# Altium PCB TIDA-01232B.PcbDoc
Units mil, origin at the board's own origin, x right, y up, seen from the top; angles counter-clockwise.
Board outline 3000 x 3000 mil, 4 copper layers (Top Layer, Signal Layer 1, Signal Layer 2, Bottom Layer), stack 64.4 mil thick; 78 components, 21 nets, 177 pads, 127 vias.
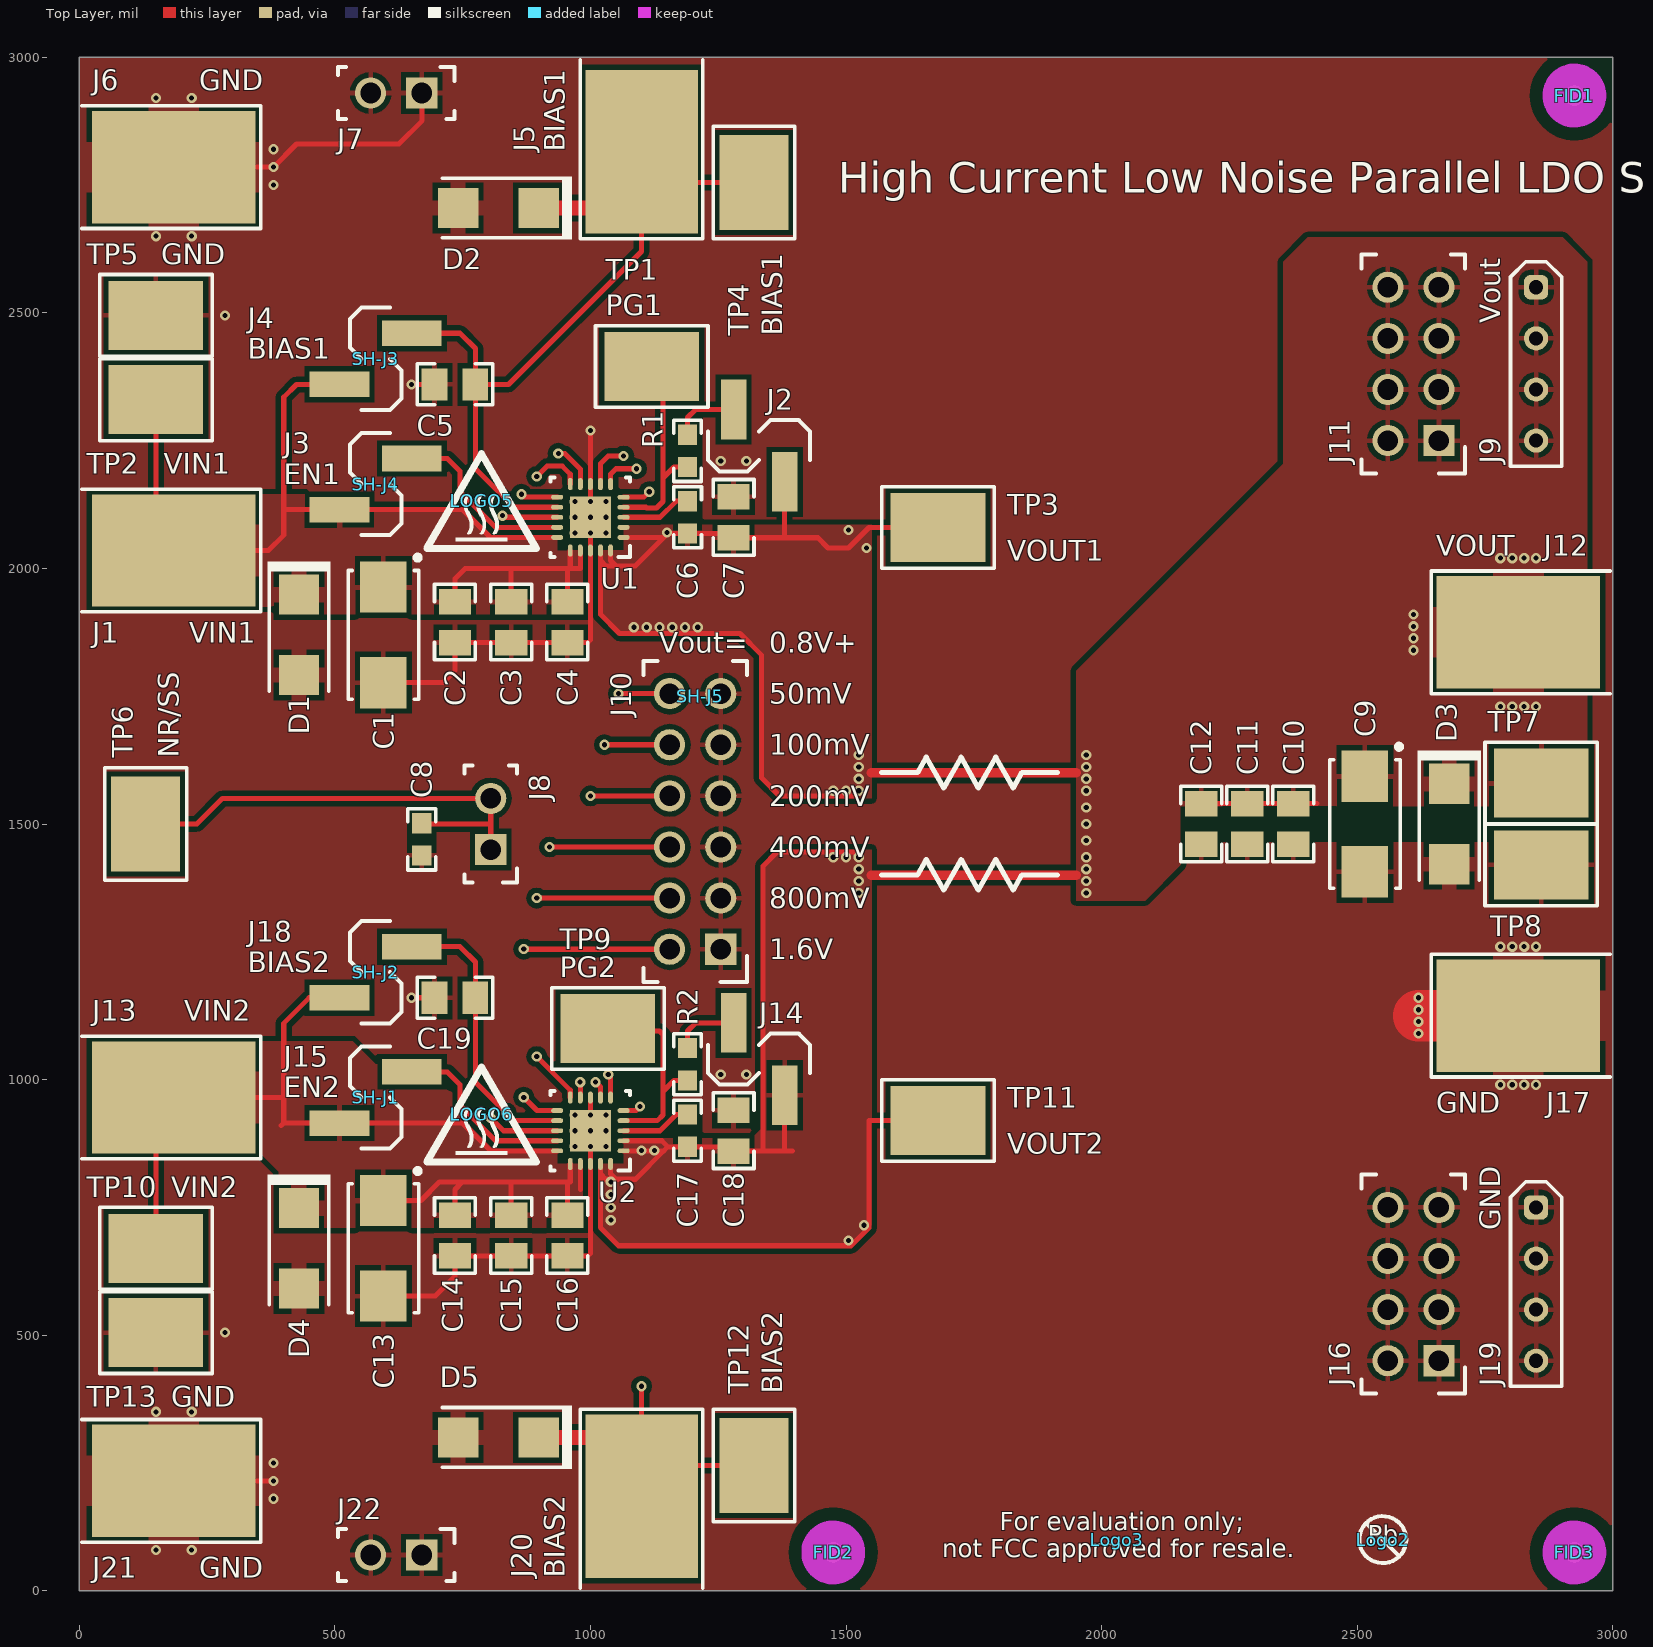
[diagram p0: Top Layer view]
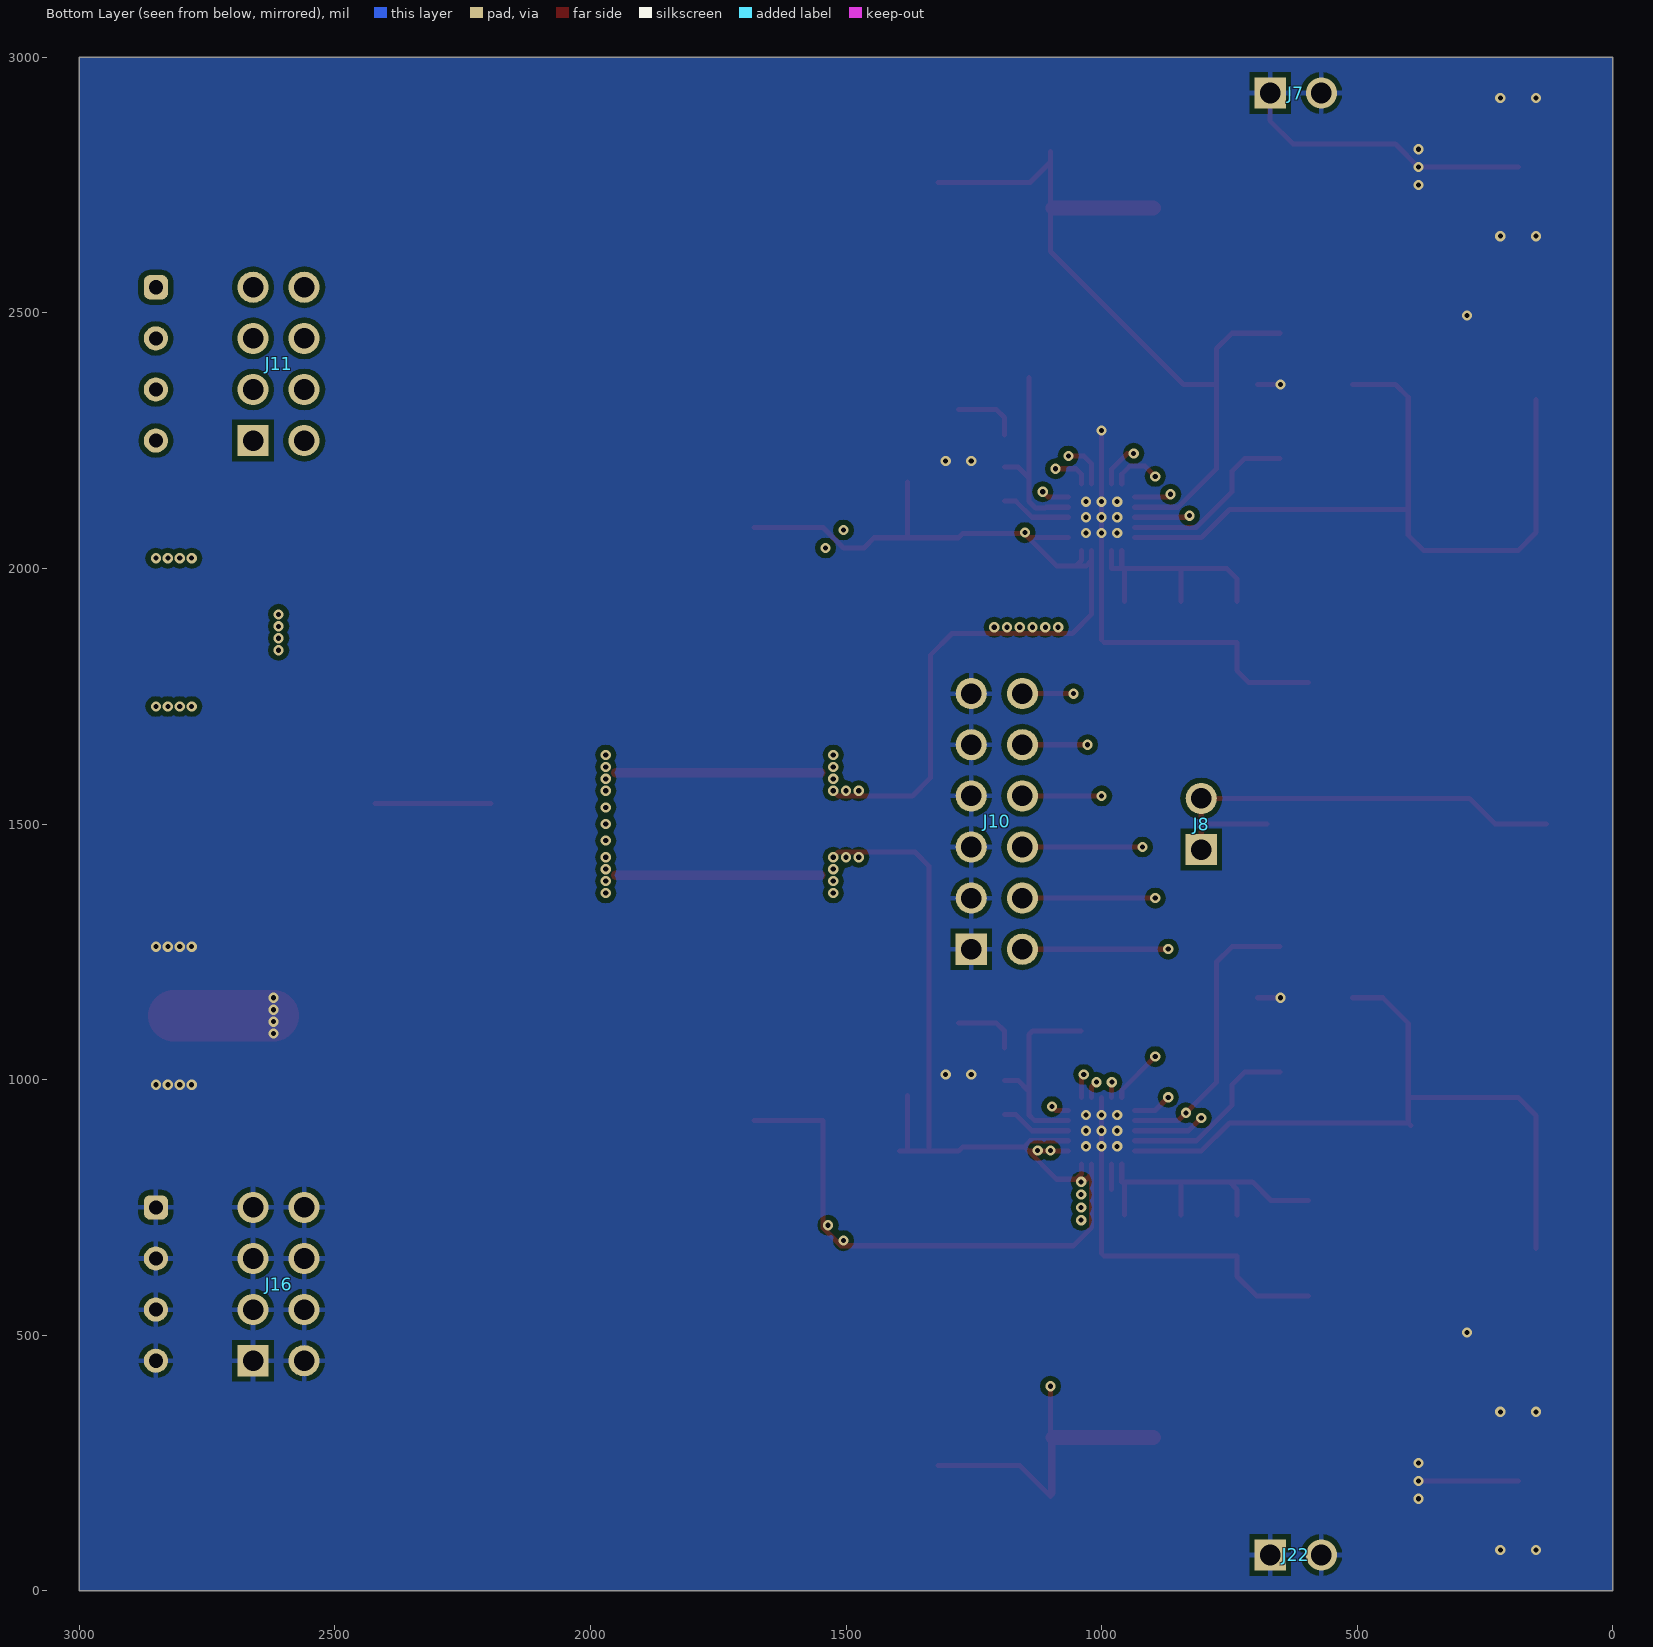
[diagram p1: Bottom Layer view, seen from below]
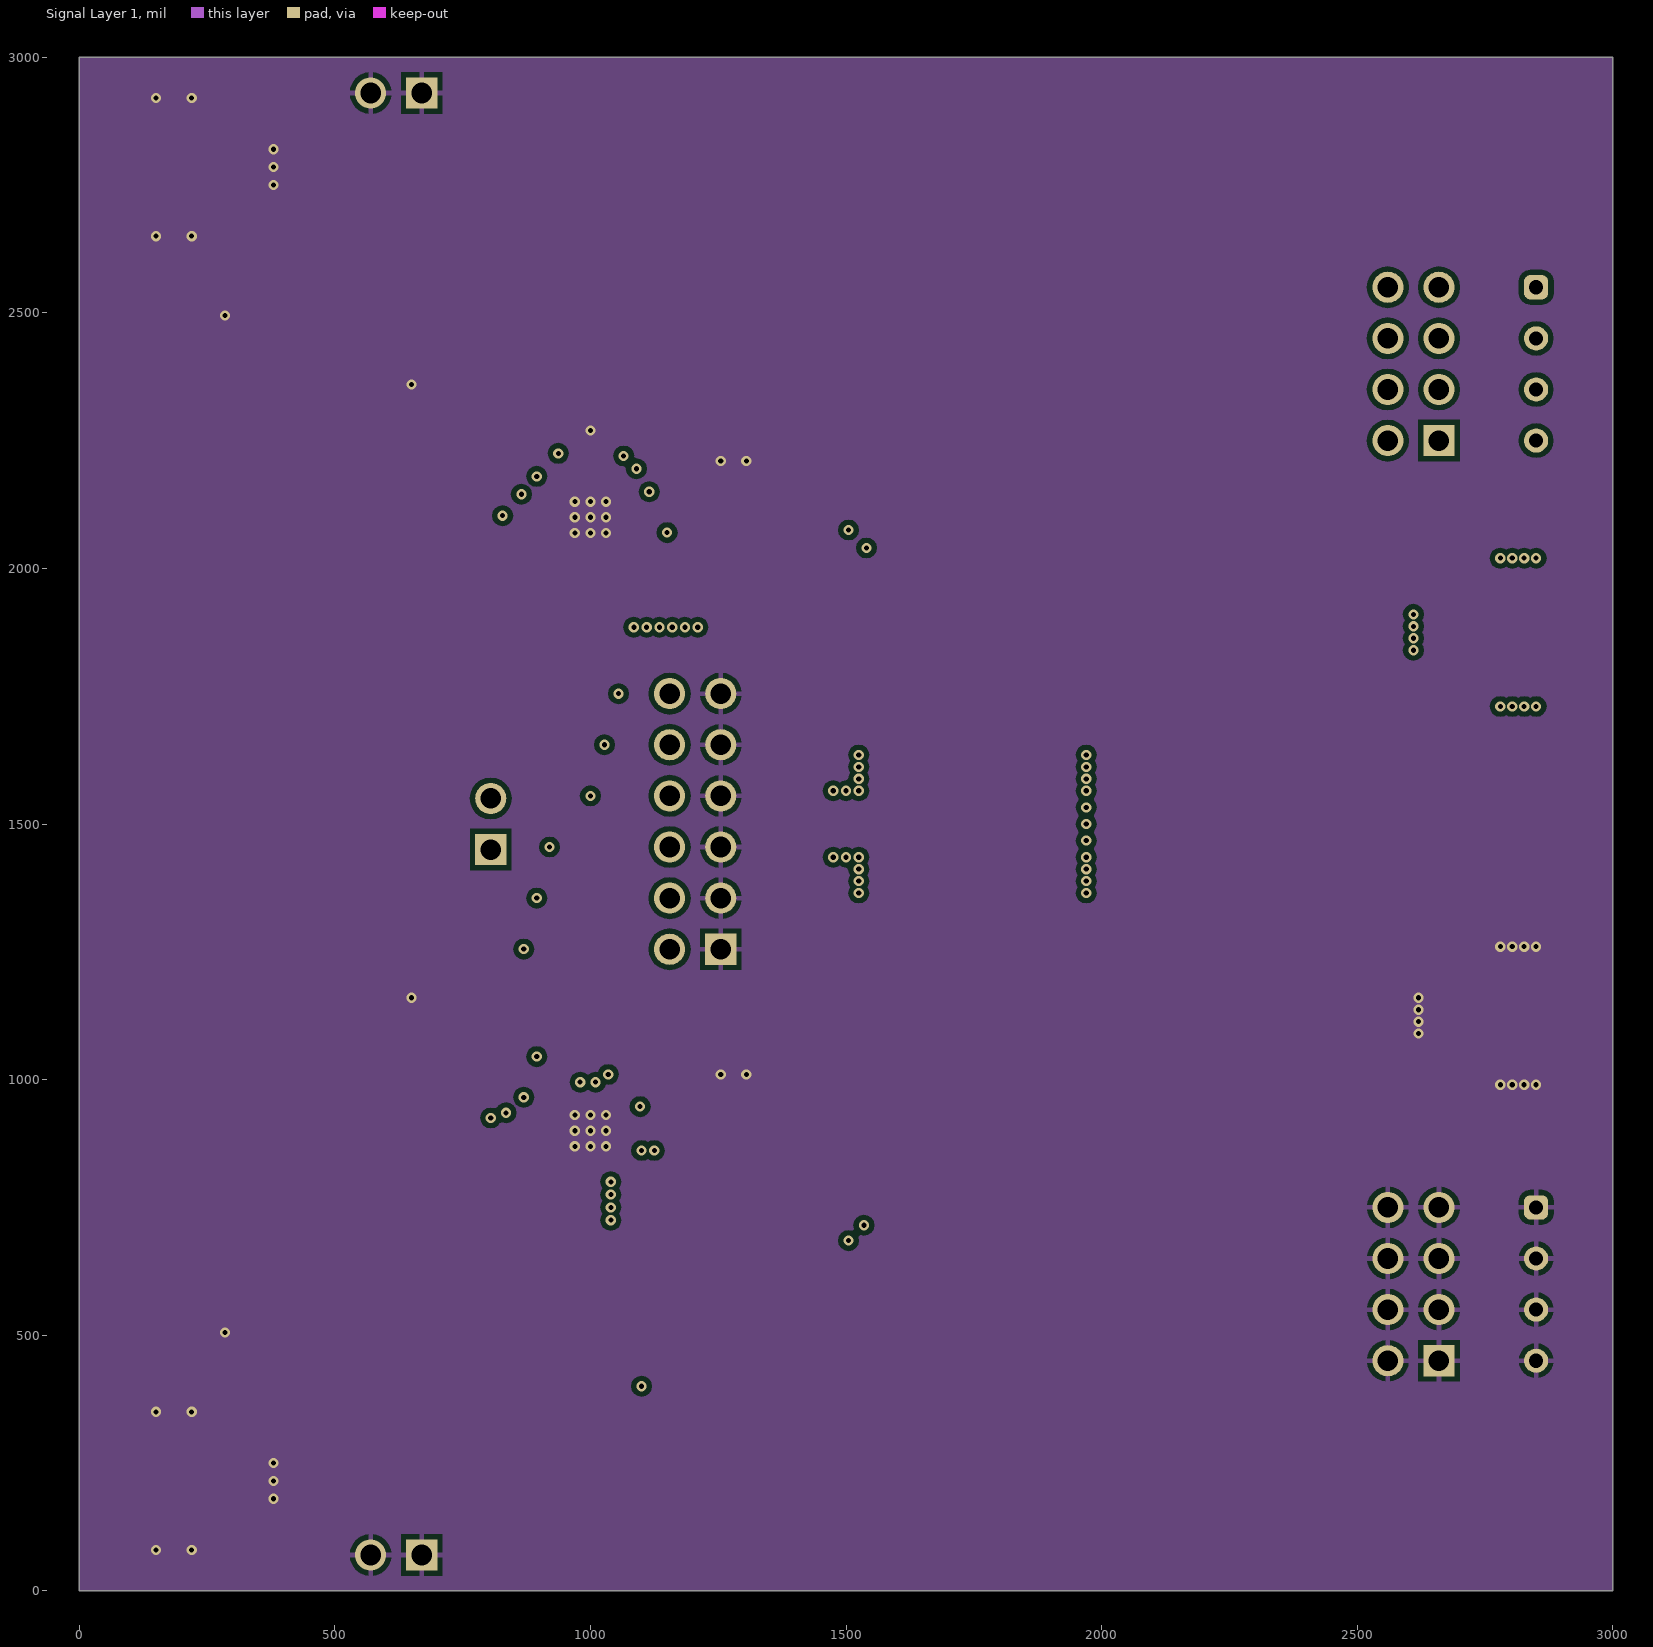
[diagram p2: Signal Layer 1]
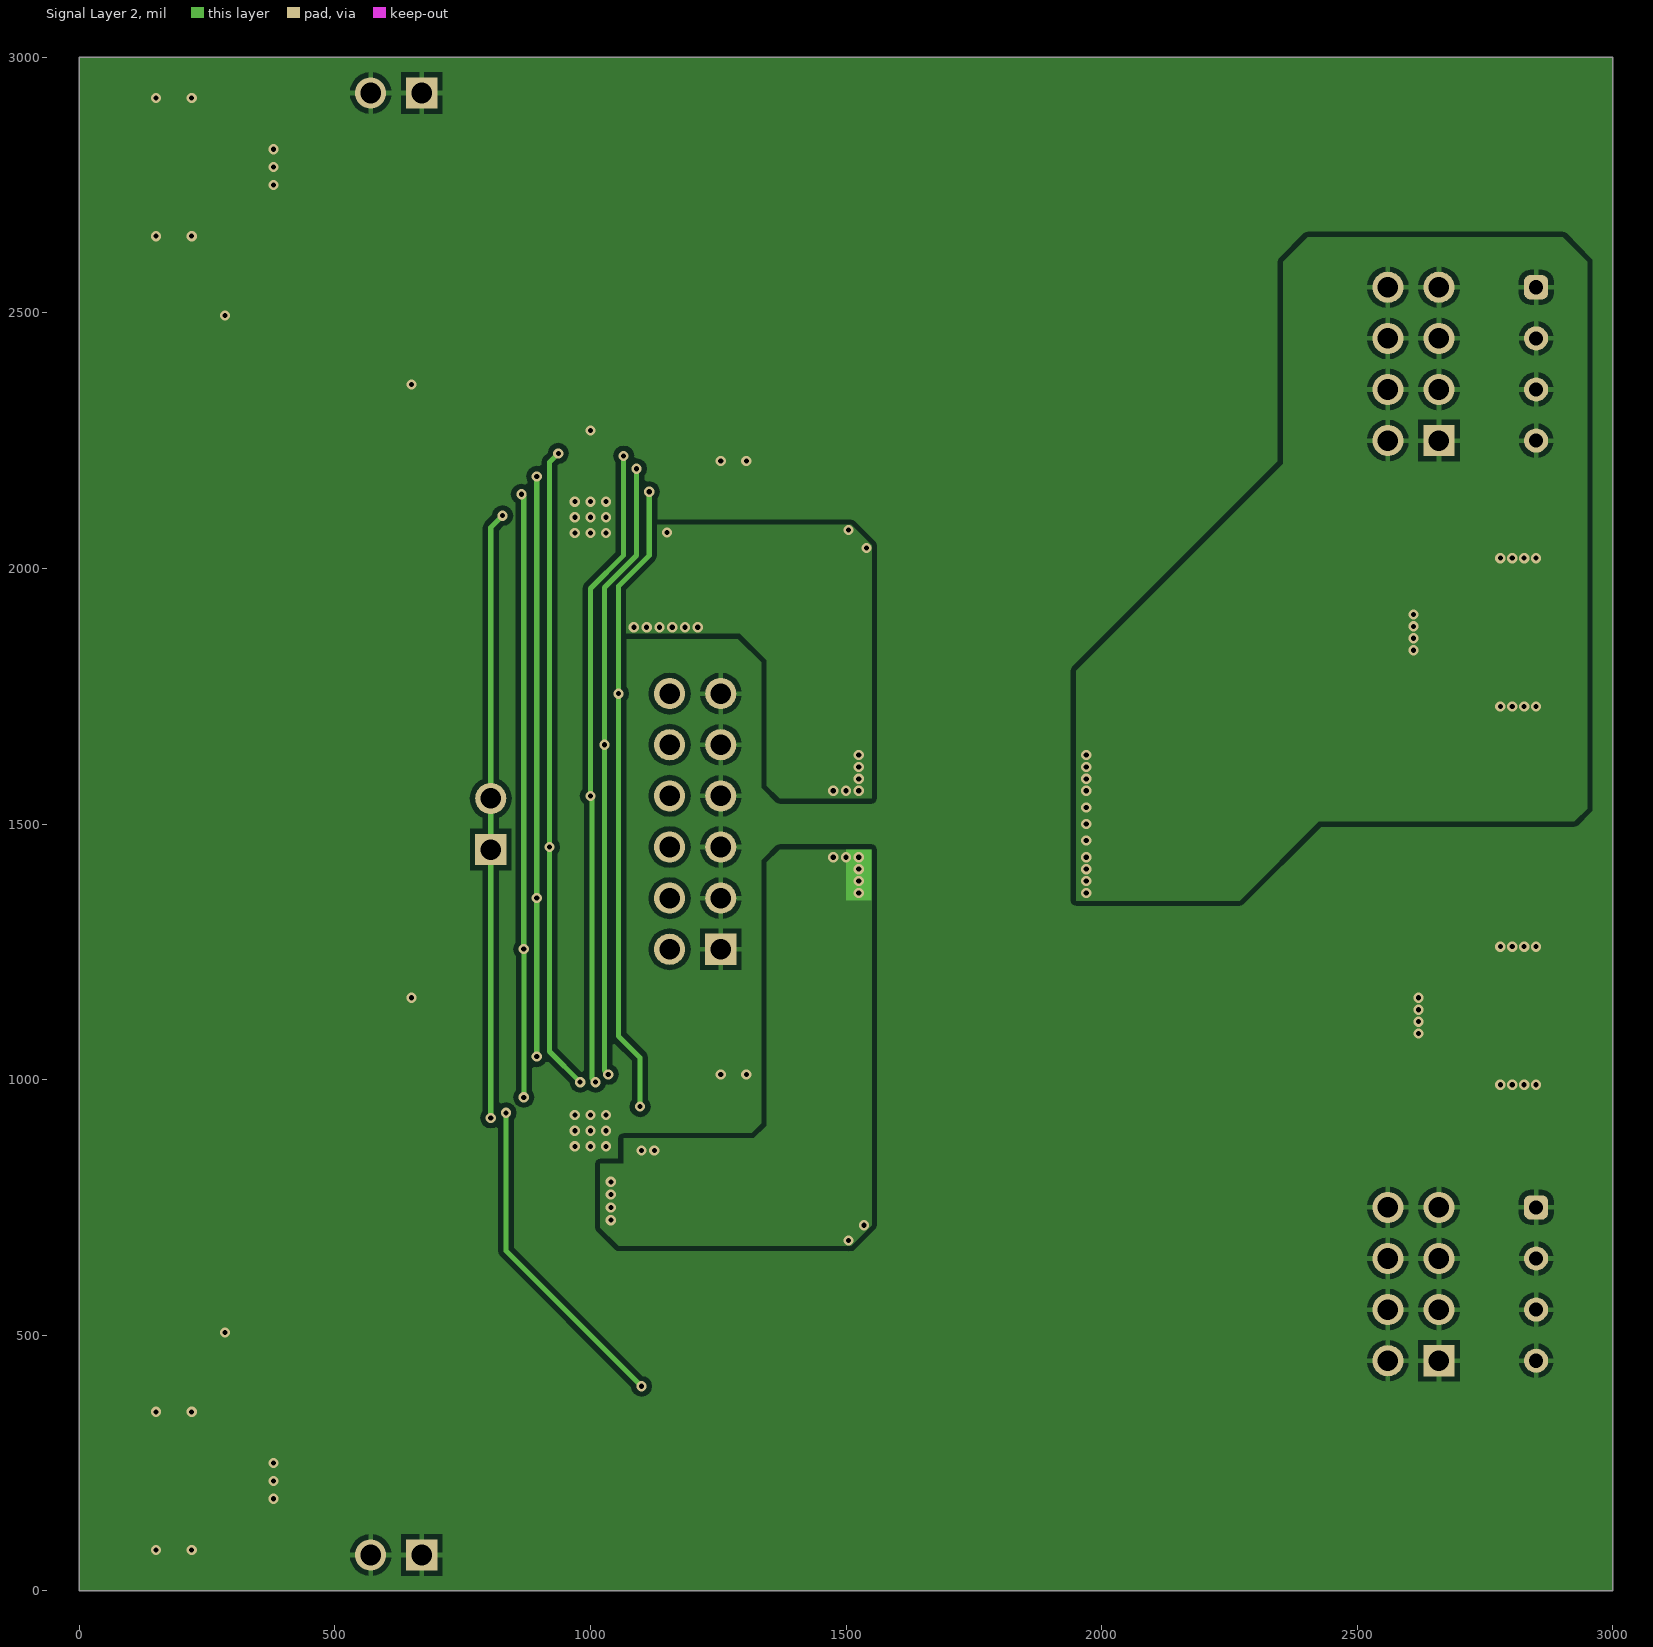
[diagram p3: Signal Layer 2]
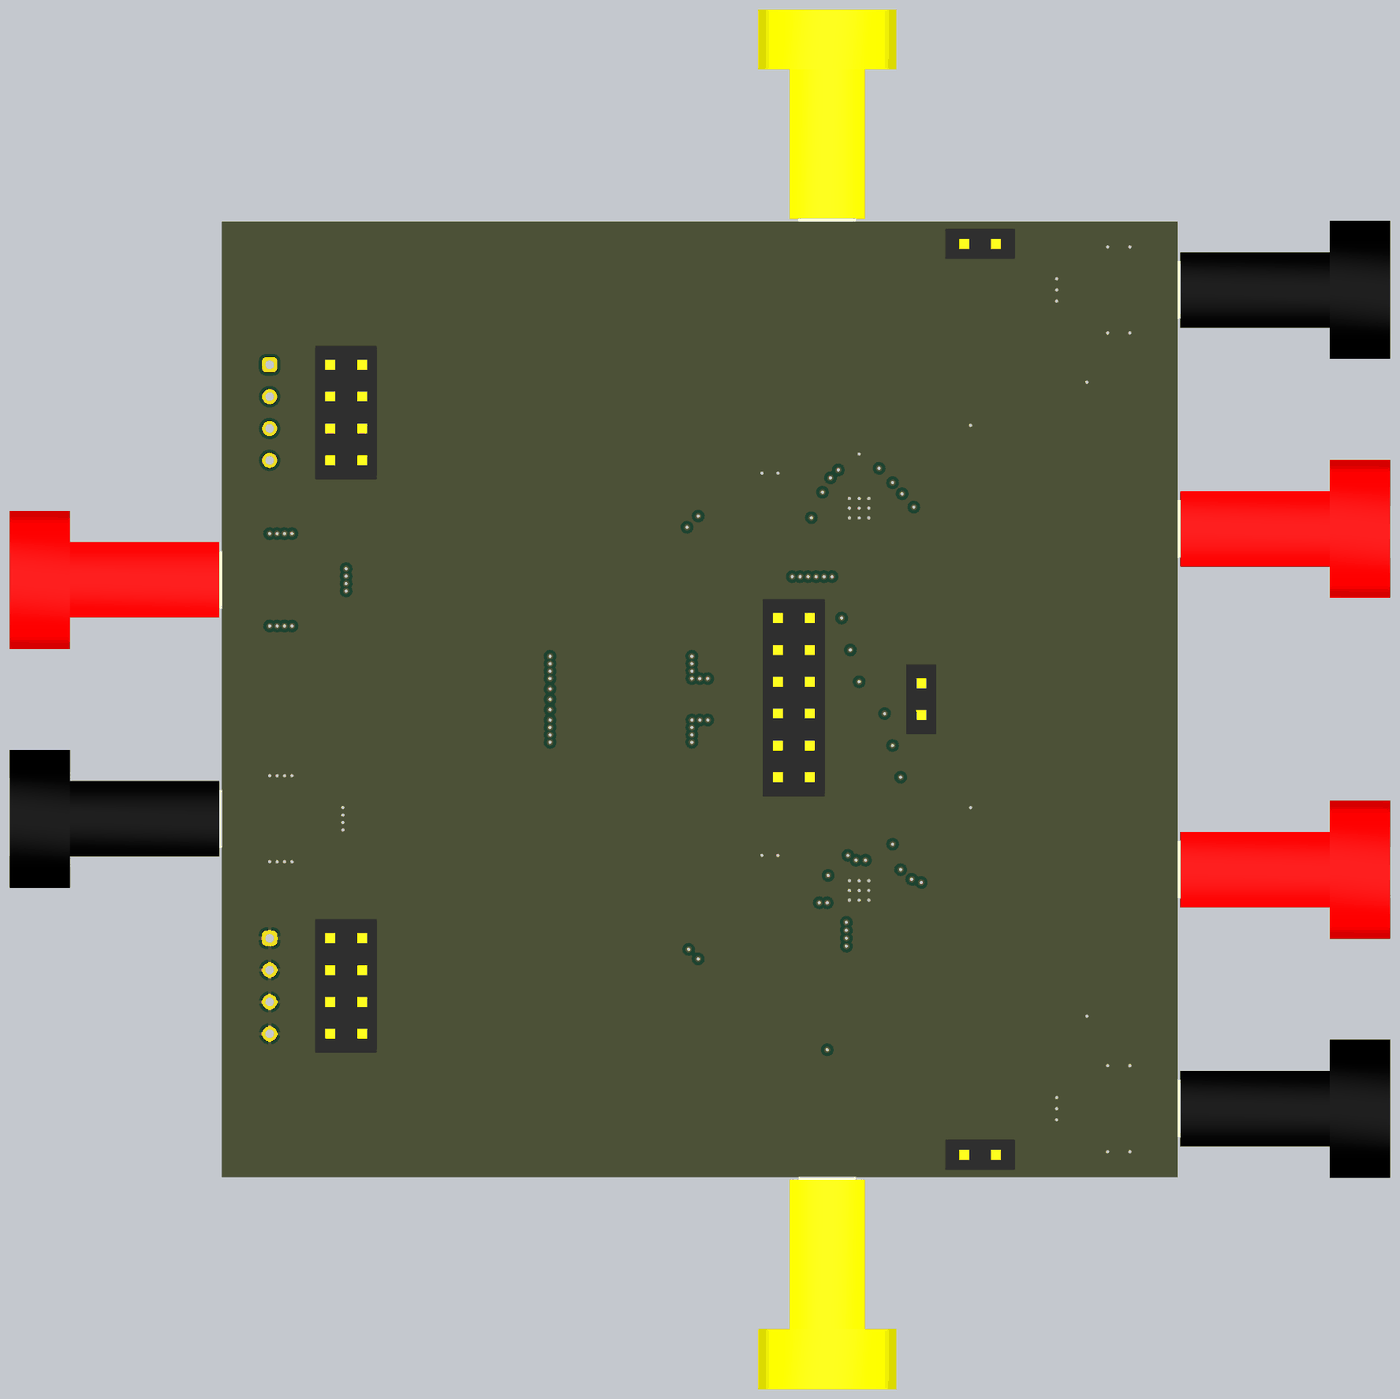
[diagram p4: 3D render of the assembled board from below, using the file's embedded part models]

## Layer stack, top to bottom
Top Solder: solder mask 0.4, Solder Resist, Dk 3.5
Top Layer: signal copper 2.8
Dielectric 1: core 8, Dk 4.2
Signal Layer 1: signal copper 1.4
Dielectric 2: prepreg 40, FR-4, Dk 4.2
Signal Layer 2: signal copper 1.4
Dielectric 3: core 8, Dk 4.2
Bottom Layer: signal copper 2.8
Bottom Solder: solder mask 1.4, Solder Resist, Dk 3.5

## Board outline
0,0 3000,0 3000,3000 0,3000

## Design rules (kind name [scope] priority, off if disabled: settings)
AcuteAngle [All] p1: minimum=4.50000000000000E+0001 checktracksonly=FALSE
AssemblyTestPointUsage [All] p1: valid=2
Clearance Clearance_Keepouts [((IsTrack Or IsArc) And Not InPoly) And IsFree and IsKeepOut vs ((IsTrack Or IsArc) And Not InPoly) And IsFree and IsKeepOut] p1: gap=0 ignorepadtopadclearanceinfootprint=FALSE
Clearance Clearance_BoardEdge_MountingHoles [OnCopper and InComponentClass('Mounting Holes') vs IsKeepOut] p2: gap=40 ignorepadtopadclearanceinfootprint=FALSE except(0: Arc-Hole Track-Hole SMDPad-Hole THPad-Hole Via-Hole Fill-Hole Poly-Hole Region-Hole Text-Hole)
Clearance Clearance_BoardEdge_Poly [OnCopper and InPoly vs IsKeepOut] p3: gap=25 ignorepadtopadclearanceinfootprint=FALSE except(0: Arc-Hole Track-Hole SMDPad-Hole THPad-Hole Via-Hole Fill-Hole Poly-Hole Region-Hole Text-Hole)
Clearance Clearance_BoardEdge [OnCopper and Not InComponentClass('Logo') and not InComponentClass('FiducialMark') and not InRegion(1000,500,4000,800) and Not IsKeepout vs IsKeepOut] p4: gap=5 ignorepadtopadclearanceinfootprint=FALSE except(0: Arc-Hole Track-Hole SMDPad-Hole THPad-Hole Via-Hole Fill-Hole Poly-Hole Region-Hole Text-Hole)
Clearance Clearance_Poly [InPolygon] p5: gap=10 ignorepadtopadclearanceinfootprint=FALSE except(0: Arc-Hole Track-Hole SMDPad-Hole THPad-Hole Via-Hole Fill-Hole Poly-Hole Region-Hole Text-Hole)
Clearance [All] p6: gap=7.87 ignorepadtopadclearanceinfootprint=FALSE except(0: Arc-Hole Track-Hole SMDPad-Hole THPad-Hole Via-Hole Fill-Hole Poly-Hole Region-Hole Text-Hole)
ComponentClearance ComponentClearance_MountingHoles_FiducialMarks [InComponentClass('Mounting Holes') vs InComponentClass('FiducialMark')] p1: gap=50 collisioncheckmode=3 verticalgap=10 showdistances=FALSE
ComponentClearance ComponentClearance_Shunt [InComponentClass('Header') vs InComponentClass('Shunt')] p2: gap=0 collisioncheckmode=3 verticalgap=0 showdistances=FALSE
ComponentClearance ComponentClearance_Shunt_1 [HasFootprint('SNT-100-BK-G')] p3: gap=0 collisioncheckmode=3 verticalgap=0 showdistances=FALSE
ComponentClearance ComponentClearance_Logo [InComponentClass('Logo')] p4: gap=50 collisioncheckmode=3 verticalgap=10 showdistances=FALSE
ComponentClearance ComponentClearance_ScrewToNut [(HasFootprint('NY PMS 440 0025 PH')) vs (HasFootprint('Keystone_1902C'))] p5: gap=5 collisioncheckmode=3 verticalgap=10 showdistances=FALSE
ComponentClearance ComponentClearance_MountingHoles [InComponentClass('Mounting Holes')] p6: gap=250 collisioncheckmode=3 verticalgap=100000 showdistances=FALSE
ComponentClearance ComponentClearance_SmallPassives [HasFootprint('0201*') or HasFootprint('0402*') or HasFootprint('0508') or HasFootprint('0603*') or HasFootprint('0612') or HasFootprint('0805*') or HasFootprint('0815*') or HasFootprint('0830*') or HasFootprint('1206*') or HasFootprint('1210*') or HasFootprint('1808*') or HasFootprint('1812*') or HasFootprint('1825*') or HasFootprint('2010*') or HasFootprint('2220*') or HasFootprint('2225*') or HasFootprint('2512*') or HasFootprint('2728*') or HasFootprint('3518*') vs HasFootprint('0201*') or HasFootprint('0402*') or HasFootprint('0508') or HasFootprint('0603*') or HasFootprint('0612') or HasFootprint('0805*') or HasFootprint('0815*') or HasFootprint('0830*') or HasFootprint('1206*') or HasFootprint('1210*') or HasFootprint('1808*') or HasFootprint('1812*') or HasFootprint('1825*') or HasFootprint('2010*') or HasFootprint('2220*') or HasFootprint('2225*') or HasFootprint('2512*') or HasFootprint('2728*') or HasFootprint('3518*')] p7: gap=20 collisioncheckmode=3 verticalgap=10 showdistances=FALSE
ComponentClearance ComponentClearance_THtoSMT [IsThruComponent vs IsSMTComponent] p8: gap=100 collisioncheckmode=3 verticalgap=30 showdistances=FALSE
ComponentClearance ComponentClearance_THtoTH [IsThruComponent vs IsThruComponent] p9: gap=118.11 collisioncheckmode=3 verticalgap=30 showdistances=FALSE
ComponentClearance [All] p10: gap=40 collisioncheckmode=3 verticalgap=10 showdistances=FALSE
DiffPairsRouting [All] p1: maxlimit=100 minlimit=10 mostfreqgap=10 toplayer_minwidth=15 toplayer_maxwidth=15 toplayer_prefwidth=15 midlayer1_minwidth=15 midlayer1_maxwidth=15 midlayer1_prefwidth=15 midlayer2_minwidth=15 midlayer2_maxwidth=15 midlayer2_prefwidth=15 bottomlayer_minwidth=15 bottomlayer_maxwidth=15 bottomlayer_prefwidth=15 maxuncoupledlength=1000
FabricationTestPointUsage TestPointUsage [All] p1: valid=2 allowmultiple=FALSE
FabricationTestpoint Testpoint [All] p1: side=3 testpointundercomponent=TRUE minsize=40 maxsize=100 preferedsize=60 minholesize=0 maxholesize=40 preferedholesize=32 testpointgrid=1 allowsidetop=TRUE allowsidebottom=TRUE usegrid=TRUE gridtolerance=0.01
FanoutControl Fanout_LCC [IsLCC] p1: bgadir=Out bgaviamode=Centered fanoutstyle=Auto fanoutdirection=Alternating viagrid=1 // Fanout_LCC (Default Rule)
FanoutControl Fanout_BGA [IsBGA] p2: bgadir=Out bgaviamode=Centered fanoutstyle=Auto fanoutdirection=Alternating viagrid=1 // Fanout_BGA (Default Rule)
FanoutControl Fanout_Default [All] p4: bgadir=Out bgaviamode=Centered fanoutstyle=Auto fanoutdirection=Alternating viagrid=1 // Fanout_Default (Default Rule)
FanoutControl Fanout_Small [(CompPinCount < 5)] p5: bgadir=Out bgaviamode=Centered fanoutstyle=Auto fanoutdirection=OutThenIn viagrid=1 // Fanout_Small (Default Rule)
HoleSize [All] p1: absolutevalues=TRUE maxlimit=251 minlimit=8 maxpercent=80.000 minpercent=20.000
MinimumAnnularRing MinimumAnnularRing_ThermalPadVias [IsVia and InAnyComponent] p1: minimumring=5
MinimumAnnularRing [All] p2: minimumring=5
MinimumSolderMaskSliver MinimumSolderMaskSliver_Logo [InComponentClass('Logo') vs InComponentClass('Logo')] p1: minsoldermaskwidth=0.7
MinimumSolderMaskSliver [All] p2: minsoldermaskwidth=3.94
PlaneClearance [All] p1: clearance=10
PlaneConnect [All] p1: planeconnectstyle=Direct reliefexpansion=10 reliefentries=4 reliefconductorwidth=10 reliefairgap=10
PolygonConnect TPS_thermals [HasFootprint('RGR0020A')] p1: connectstyle=Direct reliefconductorwidth=10 reliefentries=4 polygonreliefangle="90 Angle" airgapwidth=10
PolygonConnect VIAS [All vs IsVia] p2: connectstyle=Direct reliefconductorwidth=10 reliefentries=4 polygonreliefangle="90 Angle" airgapwidth=10
PolygonConnect BananaCon_Pow [HasFootprint('6091')] p3: connectstyle=Relief reliefconductorwidth=100 reliefentries=4 polygonreliefangle="90 Angle" airgapwidth=10
PolygonConnect BananaCon_GND [HasFootprint('6092')] p4: connectstyle=Relief reliefconductorwidth=100 reliefentries=4 polygonreliefangle="90 Angle" airgapwidth=10
PolygonConnect PolygonCon_ZD [HasFootprint('SMA')] p5: connectstyle=Relief reliefconductorwidth=30 reliefentries=4 polygonreliefangle="90 Angle" airgapwidth=10
PolygonConnect [All] p6: connectstyle=Relief reliefconductorwidth=10 reliefentries=4 polygonreliefangle="90 Angle" airgapwidth=10
RoutingVias ThermalPadVias [IsVia and InAnyComponent] p1: holewidth=8 width=18 viastyle="Through Hole" minholewidth=8 minwidth=18 maxholewidth=12.99 maxwidth=23.62
RoutingVias [All] p2: holewidth=8 width=18 viastyle="Through Hole" minholewidth=8 minwidth=18 maxholewidth=40 maxwidth=65
SilkToBoardRegionClearance [Not ((IsComment or IsDesignator) And (Hide <> 'False')) and not InRegion(1000,500,4000,800)] p1:
SilkToSilkClearance SilkToSilkClearance_Pb-FreeLogo [(HasFootprint('Pb-Free_Overlay_Medium') OR HasFootprint('Pb-Free_Overlay_Small')) vs (HasFootprint('Pb-Free_Overlay_Medium') OR HasFootprint('Pb-Free_Overlay_Small'))] p1: silktosilkclearance=0
SilkToSilkClearance [All] p2: silktosilkclearance=4
SilkToSolderMaskClearance SilkToComonentPadClearance [IsPad and InAnycomponent] p1: minsilkscreentomaskgap=5 clearancetoexposedcopper=TRUE
SilkToSolderMaskClearance "Silk to Solder Mask Opening" [All] p2: minsilkscreentomaskgap=4 clearancetoexposedcopper=FALSE
SolderMaskExpansion [All] p1: expansion=1.97
Width [All] p1: maxlimit=100 minlimit=6 preferedwidth=10 checkconnectedcopper=TRUE
14 further rules are at their usual default settings.

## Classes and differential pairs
component class FiducialMark: FID1 FID2 FID3
component class Header: J2 J3 J4 J14 J15 J18
component class TIDA-01232B_Hardware: FID1 FID2 FID3 Logo2 Logo3 LOGO5 LOGO6 SH-J1 SH-J2 SH-J3 SH-J4 SH-J5 ZZ1 ZZ2 ZZ3
component class AssemblyNote: ZZ1 ZZ2 ZZ3
component class TIDA-01232B: C1 C2 C3 C4 C5 C6 C7 C8 C9 C10 C11 C12 C13 C14 C15 C16 C17 C18 C19 D1 D2 D3 D4 D5 J1 J2 J3 J4 J5 J6 J7 J8 J9 J10 J11 J12 J13 J14 J15 J16 J17 J18 J19 J20 J21 J22 R1 R2 TP1 TP2 TP3 TP4 TP5 TP6 TP7 TP8 TP9 TP10 TP11 TP12 TP13 U1 U2
component class Shunt: SH-J1 SH-J2 SH-J3 SH-J4 SH-J5

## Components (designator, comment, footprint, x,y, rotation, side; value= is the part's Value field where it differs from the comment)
C1 "TPSC686K016R0200" 6032-28 595,1870 r270 top value=68uF
C2 "GRM21BR61C106KE15L" 0805_HV 735,1895 r270 top value=10uF
C3 "GRM21BR61C106KE15L" 0805_HV 845,1895 r270 top value=10uF
C4 "GRM219R60G476ME44D" 0805_HV 955,1895 r270 top value=47uF
C5 "GRM21BR61C106KE15L" 0805_HV 735,2360 r180 top value=10uF
C6 "GRM188R71H103KA01D" 0603 1190,2100 r270 top value=0.01uF
C7 "GRM219R60G476ME44D" 0805_HV 1280,2100 r90 top value=47uF
C8 "GRM188R71H103KA01D" 0603 670,1470 r270 top value=0.01uF
C9 "TPSC686K016R0200" 6032-28 2515,1500 r270 top value=68uF
C10 "GRM219R60G476ME44D" 0805_HV 2375,1500 r270 top value=47uF
C11 "GRM21BR61C106KE15L" 0805_HV 2285,1500 r270 top value=10uF
C12 "GRM21BR61C106KE15L" 0805_HV 2195,1500 r270 top value=10uF
C13 "TPSC686K016R0200" 6032-28 595,670 r270 top value=68uF
C14 "GRM21BR61C106KE15L" 0805_HV 735,695 r270 top value=10uF
C15 "GRM21BR61C106KE15L" 0805_HV 845,695 r270 top value=10uF
C16 "GRM219R60G476ME44D" 0805_HV 955,695 r270 top value=47uF
C17 "GRM188R71H103KA01D" 0603 1190,900 r90 top value=0.01uF
C18 "GRM219R60G476ME44D" 0805_HV 1280,900 r90 top value=47uF
C19 "GRM21BR61C106KE15L" 0805_HV 735,1160 r180 top value=10uF
D1 "SMAZ5V6-13-F" SMA 430,1870 r270 top value=5.6V
D2 "SMAZ5V6-13-F" SMA 820,2705 r180 top value=5.6V
D3 "SMAZ5V6-13-F" SMA 2680,1500 r270 top value=5.6V
D4 "SMAZ5V6-13-F" SMA 430,670 r270 top value=5.6V
D5 "SMAZ5V6-13-F" SMA 820,300 r180 top value=5.6V
FID1 "Fiducial" Fiducial10-30 2925,2925 r0 top
FID2 "Fiducial" Fiducial10-30 1475,75 r0 top
FID3 "Fiducial" Fiducial10-30 2925,75 r0 top
J1 "VIN1" 6091 0,2035 r0 top
J2 "PG1" Molex_87898-0204 1330,2240 r0 top
J3 "EN1" Molex_87898-0204 580,2165 r270 top
J4 "BIAS1" Molex_87898-0204 580,2410 r270 top
J5 "BIAS1" CONN_108-0907-001 1100,3000 r270 top
J6 "GND" 6092 0,2785 r0 top
J7 "SSQ-102-03-G-S" Samtec_SSQ-102-03-x-S 620,2930 r180 bottom
J8 "SSQ-102-03-G-S" Samtec_SSQ-102-03-x-S 805,1500 r90 bottom
J9 "Vout" Mill-Max_342-xx-104-00-591000 2850,2400 r270 top
J10 "SSQ-106-03-G-D" Samtec_SSQ-106-03-x-D 1205,1505 r90 bottom
J11 "SSQ-104-03-G-D" Samtec_SSQ-104-03-x-D 2610,2400 r90 bottom
J12 "VOUT" 6091 3000,1875 r180 top
J13 "VIN2" 6091 0,965 r0 top
J14 "PG2" Molex_87898-0204 1330,1040 r0 top
J15 "EN2" Molex_87898-0204 580,965 r270 top
J16 "SSQ-104-03-G-D" Samtec_SSQ-104-03-x-D 2610,600 r90 bottom
J17 "GND" 6092 3000,1125 r180 top
J18 "BIAS2" Molex_87898-0204 580,1210 r270 top
J19 "GND" Mill-Max_342-xx-104-00-591000 2850,600 r270 top
J20 "BIAS2" CONN_108-0907-001 1100,0 r90 top
J21 "GND" 6092 0,215 r0 top
J22 "SSQ-102-03-G-S" Samtec_SSQ-102-03-x-S 620,70 r180 bottom
Logo2 "Pb-Free Symbol" Pb-Free_Overlay_Small 2550,100 r0 top
Logo3 "FCC disclaimer" FCC_disclaimer_stacked 2030,100 r0 top
LOGO5 "CAUTION HOT SURFACE" IEC_HotSurface_Small 787,2132 r0 top
LOGO6 "CAUTION HOT SURFACE" IEC_HotSurface_Small 787,932 r0 top
R1 "CRCW060310K0FKEA" 0603 1190,2230 r90 top value=10.0k
R2 "CRCW060310K0FKEA" 0603 1190,1030 r90 top value=10.0k
SH-J1 "969102-0000-DA" SNT-100-BK-G 580,965 r90 top value=1x2
SH-J2 "969102-0000-DA" SNT-100-BK-G 580,1210 r90 top value=1x2
SH-J3 "969102-0000-DA" SNT-100-BK-G 580,2410 r90 top value=1x2
SH-J4 "969102-0000-DA" SNT-100-BK-G 580,2165 r90 top value=1x2
SH-J5 "969102-0000-DA" SNT-100-BK-G 1214.8,1750 r180 top value=1x2
TP1 "PG1" Testpoint_Keystone_Compact 1120,2395 r180 top value=SMT
TP2 "VIN1" Testpoint_Keystone_Compact 150,2330 r180 top value=SMT
TP3 "VOUT1" Testpoint_Keystone_Compact 1680,2080 r180 top value=SMT
TP4 "BIAS1" Testpoint_Keystone_Compact 1320,2755 r270 top value=SMT
TP5 "GND" Testpoint_Keystone_Compact 150,2495 r180 top value=SMT
TP6 "NR/SS" Testpoint_Keystone_Compact 130,1500 r90 top value=SMT
TP7 "VOUT" Testpoint_Keystone_Compact 2860,1580 r180 top value=SMT
TP8 "GND" Testpoint_Keystone_Compact 2860,1420 r180 top value=SMT
TP9 "PG2" Testpoint_Keystone_Compact 1034.26,1100 r180 top value=SMT
TP10 "VIN2" Testpoint_Keystone_Compact 150,670 r180 top value=SMT
TP11 "VOUT2" Testpoint_Keystone_Compact 1680,920 r180 top value=SMT
TP12 "BIAS2" Testpoint_Keystone_Compact 1320,245 r270 top value=SMT
TP13 "GND" Testpoint_Keystone_Compact 150,505 r0 top value=SMT
U1 "TPS7A8500RGRR" RGR0020A 1000,2100 r180 top
U2 "TPS7A8500RGRR" RGR0020A 1000,900 r180 top
ZZ1 "These assemblies are ESD sensitive, ESD precautions shall be observed." AssemblyNote -505,3930 r0 top
ZZ2 "These assemblies must be clean and free from flux and all contaminants. Use of no clean flux is not acceptable." AssemblyNote -505,4172.5 r0 top
ZZ3 "These assemblies must comply with workmanship standards IPC-A-610 Class 2, unless otherwise specified." AssemblyNote -505,4415 r0 top

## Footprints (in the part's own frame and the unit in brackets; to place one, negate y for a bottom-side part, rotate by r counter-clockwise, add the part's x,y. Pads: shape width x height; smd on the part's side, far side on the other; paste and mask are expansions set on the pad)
0603 [mm] "0603 from SM-752 data"
  rect 1x0.95 smd: 1(-0.8,0) 2(0.8,0)
  silkscreen extent -1.52,-0.69 1.52,0.69, body extent -0.87,-0.47 0.87,0.47, height 1
0805_HV [mil] "0805 with 30mil clearance between pads"
  rect 50x63 smd: 1(-40,0) 2(40,0)
  silkscreen extent -74,-40 74,40, body extent -43,-29 43,29, height 57
6032-28 [mm] "Medium Density IPC based on Vishay Sprague 293D datasheet."
  rect 2.55x2.3 smd: 1(-2.375,0) 2(2.375,0)
  silkscreen extent -3.96,-1.75 3.2,1.83, body extent -3.15,-1.75 3.15,1.75, height 2.8
6091 [mil] "Keystone Insulated End Launch Banana Jack"
  rect 320x220 smd: 1(185,0)
  silkscreen extent 5,-120 355,120, body extent -666,-216 271,216, height 227
6092 [mil] "Keystone Insulated End Launch Banana Jack"
  rect 320x220 smd: 1(185,0)
  silkscreen extent 5,-120 355,120, body extent -666,-216 271,216, height 227
AssemblyNote [mil] "Assembly Note"
CONN_108-0907-001 [mil] "Keystone Insulated End Launch Banana Jack"
  rect 320x220 smd: 1(185,0)
  silkscreen extent 5,-120 355,120, body extent -666,-216 271,216, height 227
FCC_disclaimer_stacked [mil]
Fiducial10-30 [mm]
  round 1 smd mask+1: 1(0,0)
  Top Layer keep-out circle w1.678: c0,0 r0.75
IEC_HotSurface_Small [mil]
  silkscreen extent -107,-93 107,92
Mill-Max_342-xx-104-00-591000 [mm] "Mill-Max"
  rrect50% 1.2x1.2 hole 0.7: 1(-3.81,0)
  round 1.2 hole 0.7: 2(-1.27,0) 3(1.27,0) 4(3.81,0)
  silkscreen extent -5.08,-1.27 5.08,1.27, body extent -5.08,-1.27 5.08,1.27, height 8.51
Molex_87898-0204 [mm] "Header, 2.54 mm, 2x1, R/A, SMT"
  rect 1.27x2.96 smd: 1(-1.27,1.8) 2(1.27,-1.8)
  silkscreen extent -2.54,-1.27 2.54,1.27, body extent -2.54,-2.4 2.54,2.4, height 9.65
Pb-Free_Overlay_Small [mil]
  silkscreen extent -46,-46 46,46
RGR0020A [mm] "QFN, 20-Leads, Body 3.5x3.5mm, Pitch 0.5mm, Thermal Pad 2.05x2.05mm, TI Recommended"
  oval 0.6x0.24 smd: 1(-1.65,1) 2(-1.65,0.5) 3(-1.65,0) 4(-1.65,-0.5) 5(-1.65,-1) 11(1.65,-1) 12(1.65,-0.5) 13(1.65,0) 14(1.65,0.5) 15(1.65,1)
  oval 0.24x0.6 smd: 6(-1,-1.65) 7(-0.5,-1.65) 8(0,-1.65) 9(0.5,-1.65) 10(1,-1.65) 16(1,1.65) 17(0.5,1.65) 18(0,1.65) 19(-0.5,1.65) 20(-1,1.65)
  rect 2.05x2.05 smd paste-1.025: 21(0,0)
  silkscreen extent -1.97,-1.97 1.97,1.97, body extent -1.83,-1.83 1.83,1.83, height 1.01
Samtec_SSQ-102-03-x-S [mm] "Receptacle, 2.54mm, 2x1, TH"
  rect 1.55x1.55 hole 1.02: 1(-1.27,0)
  round 1.55 hole 1.02: 2(1.27,0)
  body extent -2.79,-1.21 2.79,1.21, height 8.51
Samtec_SSQ-104-03-x-D [mm] "Receptacle, 2.54mm, 4x2, TH"
  rect 1.55x1.55 hole 1.02: 1(-3.81,1.27)
  round 1.55 hole 1.02: 2(-3.81,-1.27) 3(-1.27,1.27) 4(-1.27,-1.27) 5(1.27,1.27) 6(1.27,-1.27) 7(3.81,1.27) 8(3.81,-1.27)
  body extent -5.33,-2.48 5.33,2.48, height 8.51
Samtec_SSQ-106-03-x-D [mm] "Receptacle, 2.54mm, 6x2, TH"
  rect 1.55x1.55 hole 1.02: 1(-6.35,1.27)
  round 1.55 hole 1.02: 2(-6.35,-1.27) 3(-3.81,1.27) 4(-3.81,-1.27) 5(-1.27,1.27) 6(-1.27,-1.27) 7(1.27,1.27) 8(1.27,-1.27) 9(3.81,1.27) 10(3.81,-1.27) 11(6.35,1.27) 12(6.35,-1.27)
  body extent -7.87,-2.48 7.87,2.48, height 8.51
SMA [mm] "Molded Diode, 2-Leads, Body 4.3x2.6mm, IPC Medium Density, based on OnSemi component dimensions and land pattern"
  rect 2x2 smd: 1(-2,0) 2(2,0)
  silkscreen extent -3.66,-1.57 2.79,1.57, body extent -2.6,-1.3 2.6,1.3, height 2.42
SNT-100-BK-G [mil] "Samtec STEP model"
  round 1 on Mech3: 0(0,0)
  body extent -100,-50 100,50, height 344
Testpoint_Keystone_Compact [mil] "Compact SMT test point"
  rect 185x135 smd: 1(0,0)
  silkscreen extent -110,-80 110,80, body extent -75,-56 75,56, height 91

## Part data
C1 C9 C13: "CAP, TA, 68 µF, 16 V, +/- 10%, 0.2 ohm, SMD", Cap_Case=C, Manufacturer=AVX, Supplier Part Number 1=478-1774-1-ND, Tolerance_%=10, Value1="0.2 ohm", Value2=16V, ValueDisplayed=68µF
C2 C3 C5 C11 C12 C14 C15 C19: "CAP, CERM, 10 µF, 16 V, +/- 10%, X5R, 0805", Cap_Case=0805, Manufacturer=MuRata, Supplier Part Number 1=490-3886-1-ND, TempCo=X5R, Tolerance_%=10, Value1="0.008 ohm", Value2=16V, ValueDisplayed=10µF
C4 C7 C10 C16 C18: "CAP, CERM, 47 µF, 4 V, +/- 20%, X5R, 0805", Cap_Case=0805, Manufacturer=MuRata, Supplier Part Number 1=490-9949-2-ND, TempCo=X5R, Tolerance_%=20, Value1=Unknown, Value2=4V, ValueDisplayed=47µF
C6 C8 C17: "CAP, CERM, 0.01 µF, 50 V, +/- 10%, X7R, 0603", Cap_Case=0603, Manufacturer=MuRata, Supplier Part Number 1=490-1512-1-ND, TempCo=X7R, Tolerance_%=10, Value1=Unknown, Value2=50V, ValueDisplayed=0.01µF
D1 D2 D3 D4 D5: "Diode, Zener, 5.6 V, 1 W, SMA", Manufacturer="Diodes Inc.", Power_W=1, Supplier Part Number 1=SMAZ5V6-FDICT-ND, Value1=1W
FID1 FID2 FID3: "Fiducial mark.  There is nothing to buy or mount.", Manufacturer=N/A
J1 J12 J13: library part 6091, "Standard Banana Jack, Insulated, Red", Manufacturer=Keystone, Supplier Part Number 1=6091K-ND
J2 J3 J4 J14 J15 J18: library part 87898-0204, "Header, 2.54 mm, 2x1, Gold, R/A, SMT", Manufacturer=Molex, Supplier Part Number 1=WM9852-ND
J5 J20: library part 108-0907-001, "BANANA JACK, 15A, Insulated, Nylon,Yellow", Manufacturer="Emerson Network Power", Supplier Part Number 1=J154-ND
J6 J17 J21: library part 6092, "Standard Banana Jack, Insulated, Black", Manufacturer=Keystone, Supplier Part Number 1=6092K-ND
J7 J8 J22: "Receptacle, 2.54mm, 2x1, Gold, TH", Color=Black, Current_A=6.3, Manufacturer=Samtec, Supplier Part Number 1=SAM1198-02-ND
J9 J19: library part 342-10-104-00-591000, "Header, 100mil, 4x1, Gold, TH", Manufacturer=Mill-Max, Supplier Part Number 1=ED10004-ND
J10: "Receptacle, 2.54mm, 6x2, Gold, TH", Color=Black, Current_A=6.3, Manufacturer=Samtec, Supplier Part Number 1=SAM1196-06-ND
J11 J16: "Receptacle, 2.54mm, 4x2, Gold, TH", Color=Black, Current_A=6.3, Manufacturer=Samtec, Supplier Part Number 1=SAM1196-04-ND
Logo2: library part Pb-Free
Logo3: library part FCC_disclaimer, "FCC_disclaimer"
LOGO5 LOGO6: library part IEC_HotSurface, "IEC 61010-1 Hot Surface Warning"
R1 R2: "RES, 10.0 k, 1%, 0.1 W, 0603", Manufacturer=Vishay-Dale, Power_W=0.1, Supplier Part Number 1=541-10.0KHCT-ND, TempCo="100 ppm/C", Tolerance_%=1, Value1=1%, Value2=0.1W, Value_Code=10k0, ValueDisplayed=10.0k
SH-J1 SH-J2 SH-J3 SH-J4 SH-J5: "Shunt, 100mil, Gold plated, Black", Alternate Manufacturer=Samtec, Alternate PartNumber=SNT-100-BK-G, Manufacturer=3M, Supplier Part Number 1=3M9580-ND
TP1 TP2 TP3 TP4 TP5 TP6 TP7 TP8 TP9 TP10 TP11 TP12 TP13: library part 5016, "Test Point, Compact, SMT", Manufacturer=Keystone, Supplier Part Number 1=5016KCT-ND
U1 U2: "4-A, 6-µVRMS, RF, LDO Voltage Regulator, RGR0020A", Alternate Manufacturer="Texas Instruments", Alternate PartNumber=TPS7A8500RGRT
ZZ1 ZZ2 ZZ3: library part AssemblyNote, Alternate Manufacturer=-

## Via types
v1: diameter 20, hole 10, Top Layer to Bottom Layer, tented both sides, 127 vias

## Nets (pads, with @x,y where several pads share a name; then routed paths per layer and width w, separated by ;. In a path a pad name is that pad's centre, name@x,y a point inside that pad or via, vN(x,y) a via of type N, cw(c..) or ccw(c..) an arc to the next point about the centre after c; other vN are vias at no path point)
GND: C1.2 C2.2 C3.2 C4.2 C5.2 C7.2 C8.2 C9.2 C10.2 C11.2 C12.2 C13.2 C14.2 C15.2 C16.2 C18.2 C19.2 D1.2 D2.2 D3.2 D4.2 D5.2 J6.1 J7.1 J7.2 J10.1 J10.3 J10.5 J10.7 J10.9 J10.11 J16.1 J16.2 J16.3 J16.4 J16.5 J16.6 J16.7 J16.8 J17.1 J19.1 J19.2 J19.3 J19.4 J21.1 J22.1 J22.2 TP5.1 TP8.1 TP13.1 U1.8 U1.18 U1.21 U2.8 U2.18 U2.21 | length 2693.3
  Top Layer w10: J21.1 v1(380,215) ; J6.1 v1(380,2785) 425,2830 529.13,2830 625,2830 670.87,2875.87 J7.1@670.87,2930 ; C13.2 696.5,576.5 735,615 C14.2 C15.2 C16.2 995,655 ; C1.2 711.5,1776.5 735,1800 C2.2 C3.2 C4.2 995,1855 ; v1(650,1160) C19.2 ; v1(650,2360) C5.2 ; 1000,660 U2.8 ; 1000,1860 U1.18 v1(1000,2069.49) v1(1000,2100) v1(1000,2130.51) U1.8 v1(1000,2270)
  Top Layer w100: 2620,1125 J17.1
  other v1: 150,80 220,80 380,180 380,250 150,350 220,350 285,505 969.49,869.49 1000,869.49 1030.51,869.49 969.49,900 1000,900 1030.51,900 969.49,930.51 1000,930.51 1030.51,930.51 2780,990 2803.33,990 2826.67,990 2850,990 1255,1010 1305,1010 2620,1090 2620,1113.33 2620,1136.67 2620,1160 2780,1260 2803.33,1260 2826.67,1260 2850,1260 969.49,2069.49 1030.51,2069.49 969.49,2100 1030.51,2100 969.49,2130.51 1030.51,2130.51 1255,2210 1305,2210 285,2495 150,2650 220,2650 380,2750 380,2820 150,2920 220,2920
NetC1_1: C1.1 C2.1 C3.1 C4.1 D1.1 J1.1 J3.2 J4.2 TP2.1 U1.15 U1.16 U1.17 | length 1982.7
  Top Layer w10: TP2.1 150,2070 J1.1 370,2035 400,2065 400,2335 425,2360 J4.2 ; 400,2115 750,2115 804.37,2060.63 U1.15 ; C2.1 735,1980 755,2000 845,2000 ; C3.1 845,2000 ; C4.1 955,2000 ; U1.16 960.63,2000 ; U1.17 980.31,2000 960.63,2000 ; 845,2000 955,2000 ; 955,2000 960.63,2000
NetC5_1: C5.1 D2.1 J4.1 J5.1 TP4.1 U1.12 | length 1630.4
  Top Layer w10: J4.1 745,2460 775,2430 C5.1 ; U1.12 850.31,2119.69 775,2195 C5.1 ; J5.1@1095,2705 J5.1@1100,2710 ; J5.1 J5.1@1100,2795 ; TP4.1 1140,2755 J5.1@1100,2795 ; C5.1 840,2360 1100,2620 J5.1@1100,2710 ; J5.1@1100,2710 J5.1@1100,2795
  Top Layer w30: D2.1 J5.1@1095,2705
NetC6_1: C6.1 U1.3 | length 138.1
  Top Layer w10: U1.3 1136.21,2100 1167.71,2131.5 C6.1
NetC6_2: C6.2 C7.1 C9.1 C10.1 C11.1 C12.1 C17.1 C18.1 D3.1 J2.2 J9.1 J9.2 J9.3 J9.4 J11.1 J11.2 J11.3 J11.4 J11.5 J11.6 J11.7 J11.8 J12.1 J14.2 TP3.1 TP7.1 TP11.1 U1.1 U1.2 U1.19 U1.20 U2.1 U2.2 U2.19 U2.20 | length 5460.2
  Top Layer w10: U2.19 1019.69,815.32 ; U1.19 1019.69,2015.31 ; U2.20 1039.37,815.63 1050,805 ; U1.20 1039.37,2015.63 1050,2005 ; U2.1 1143.62,860.63 ; U2.2 1139.69,880.32 1151.5,868.5 ; U1.1 1143.62,2060.63 ; 1345,2060 C7.1 ; 1380,862.5 J14.2 ; J2.2 1380,2060 ; 1395,860 1337.5,860 ; v1(1525,1435) 1515,1445 1365,1445 1337.5,1417.5 1337.5,860 ; v1(1525,1565) 1515,1555 1370,1555 1335,1590 1335,1830.28 1292.4,1872.87 1057.13,1872.87 1019.69,1910.31 1019.69,2015.31 ; TP11.1 1545,920 1545,710 1510,675 1055,675 1019.69,710.31 1019.69,815.32 ; TP3.1 1545,2080 1505,2040 1465,2040 1445,2060 1380,2060 ; C12.1 C11.1 C10.1 2421.26,1540 ; 1019.69,815.32 1030,805 1050,805 ; 1019.69,2015.31 1030,2005 1050,2005 ; 1050,805 1087.99,805 1143.62,860.63 ; 1050,2005 1087.99,2005 1143.62,2060.63 ; 1143.62,860.63 1151.5,868.5 ; 1143.62,2060.63 1151.5,2068.5 C6.2 1271.5,2068.5 C7.1 ; 1151.5,868.5 1271.5,868.5 C18.1 1337.5,860 ; C7.1 1380,2060
  Top Layer w19: 1550,1400 1950,1400 ; 1550,1600 1950,1600
  other v1: 1505,685 1535,715 1040,725 1040,750 1040,775 1040,800 1100,861.26 1125,861.26 1525,1365 1970,1365 1525,1388.33 1970,1388.33 1525,1411.67 1970,1411.67 1475,1435 1500,1435 1970,1435 1970,1467.5 1970,1500 1970,1532.5 1475,1565 1500,1565 1970,1565 1525,1588.33 1970,1588.33 1525,1611.67 1970,1611.67 1525,1635 1970,1635 2780,1730 2803.33,1730 2826.67,1730 2850,1730 2610,1840 2610,1863.33 1085,1885 1110,1885 1135,1885 1160,1885 1185,1885 1210,1885 2610,1886.67 2610,1910 2780,2020 2803.33,2020 2826.67,2020 2850,2020 1540,2040 1150,2070 1505,2075
NetC8_1: C8.1 J8.1 J8.2 TP6.1 U1.13 U2.13 | length 2370.1
  Top Layer w10: TP6.1 230,1500 280,1550 J8.2 805,1500 ; C8.1@676.5,1500 805,1500 ; v1(805,925) 830,900 U2.13 ; J8.1 805,1500 ; v1@830,2105 v1(828.2,2103.2) 828.2,2098.2 830,2100 U1.13
  Signal Layer 2 w10: v1(805,925) J8.1 J8.2 805,2080 v1@830,2105
NetC13_1: C13.1 C14.1 C15.1 C16.1 D4.1 J13.1 J15.2 J18.2 TP10.1 U2.15 U2.16 U2.17 | length 2110.7
  Top Layer w10: TP10.1 150,930 J13.1 400,965 ; 395,910 400,915 ; J18.2 450,1160 400,1110 400,965 ; C13.1 668.5,763.5 705,800 750,800 ; 735,765 C14.1 735,785 750,800 ; C15.1 845,800 ; U2.15 804.37,860.63 750,915 J15.2 400,915 ; C16.1 955,800 ; U2.16 960.63,800 955,800 ; 980.32,785.32 U2.17 ; 400,915 400,965 ; 750,800 845,800 ; 845,800 955,800
NetC17_2: C17.2 U2.3 | length 138.1
  Top Layer w10: U2.3 1136.21,900 1167.71,931.5 C17.2
NetC19_1: C19.1 D5.1 J18.1 J20.1 TP12.1 U2.12 | length 1980.7
  Top Layer w10: J18.1 745,1260 775,1230 775,995 850.32,919.69 U2.12 ; J20.1@1095,300 1095,190 J20.1 ; v1(1100,400) J20.1 ; TP12.1 1160,245 J20.1
  Top Layer w30: D5.1 J20.1@1095,300
  Signal Layer 2 w10: v1(835,935) 835,665 v1(1100,400)
NetJ2_1: J2.1 R1.2 | length 130.1
  Top Layer w10: R1.2 1190,2295 1205.87,2310.87 J2.1
NetJ3_1: J3.1 U1.14 | length 363.5
  Top Layer w10: J3.1 720,2215 745,2190 745,2150 815,2080 U1.14
NetJ10_2: J10.2 U1.11 U2.11 | length 1608
  Top Layer w10: v1(865,2145) 870.63,2139.37 U1.11 ; v1@870,965 895.63,939.37 U2.11 ; v1@870,1255 J10.2
  Signal Layer 2 w10: v1(869.69,1255.31) v1@869.69,2140.31 ; v1@870,965 v1@870,1255
  other v1: 869.69,965.31
NetJ10_4: J10.4 U1.10 U2.10 | length 1613.8
  Top Layer w10: v1(895,1045) 960.63,979.37 U2.10 ; v1(895,1355) 1157.5,1355 J10.4@1160.51,1351.99 ; v1(895,2180) 915,2200 945,2200 960.63,2184.37 U1.10
  Signal Layer 2 w10: v1@890,1045 v1(895,1045) v1(895,1355) v1(895,2180)
NetJ10_6: J10.6 U1.9 U2.9 | length 1612.5
  Top Layer w10: v1(920,1455) J10.6 ; v1(937.24,2225) 950,2225 980.31,2194.69 U1.9 ; v1(980,995) 980.31,994.69 U2.9
  Signal Layer 2 w10: v1(937.24,2225) 920,2207.76 v1(920,1455) 920,1055 v1(980,995)
NetJ10_8: J10.8 U1.7 U2.7 | length 1539
  Top Layer w10: v1(1000,1555) J10.8@1157.5,1555 ; v1(1010,995) 1019.69,985.31 U2.7 ; U1.7 1019.69,2204.69 1035,2220 v1(1065,2220)
  Signal Layer 2 w10: v1(1010,995) 1002.87,1002.13 1002.87,1552.13 v1(1000,1555) 1000,1960.56 1065,2025.56 v1(1065,2220)
NetJ10_10: J10.10 U1.6 U2.6 | length 1474.9
  Top Layer w10: v1@1025,1655 v1(1027.5,1655) 1157.5,1655 J10.10@1160.51,1651.99 ; v1@1032.97,1007.97 v1(1035,1010) 1039.37,1005.63 U2.6 ; U1.6 1039.37,2184.37 1050,2195 v1(1090,2195)
  Signal Layer 2 w10: v1(1035,1010) 1027.5,1017.5 v1(1027.5,1655) 1027.5,1962.78 1090,2025.28 v1(1090,2195)
NetJ10_12: J10.12 U1.5 U2.5 | length 1443.9
  Top Layer w10: v1(1055,1755) J10.12@1157.5,1755 ; U2.5 1089.37,939.37 v1(1097.19,947.19) ; U1.5 1104.37,2139.37 v1(1115,2150) ; J10.12@1158.01,1754.49 J10.12@1162.5,1750
  Signal Layer 2 w10: v1(1097.19,947.19) 1097.19,1042.81 1055,1085 v1(1055,1755) 1055,1965 1115,2025 v1(1115,2150)
NetJ14_1: J14.1 R2.2 | length 130.1
  Top Layer w10: R2.2 1190,1095 1205.87,1110.87 J14.1
NetJ15_1: J15.1 U2.14 | length 363.7
  Top Layer w10: J15.1 720,1015 745,990 745,950 815,880 815.31,880.31 U2.14
NetR1_1: R1.1 TP1.1 U1.4 | length 382.1
  Top Layer w10: U1.4 1108.44,2119.69 1110,2118.13 1129.06,2118.13 1141.87,2130.94 1141.87,2176.87 ; TP1.1@1141.87,2373.13 1141.87,2176.87 ; R1.1 1163.5,2198.5 1141.87,2176.87
NetR2_1: R2.1 TP9.1 U2.4 | length 400.6
  Top Layer w10: TP9.1@1040,1095 1135,1095 1141.87,1088.13 1141.87,976.87 ; U2.4 1130.62,919.69 1141.87,930.94 1141.87,976.87 ; R2.1 1163.5,998.5 1141.87,976.87
pads on no net: FID1.1 FID2.1 FID3.1 SH-J1.0 SH-J2.0 SH-J3.0 SH-J4.0 SH-J5.0

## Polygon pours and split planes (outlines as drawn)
GND on Top Layer "Top Layer- GND" (solid, remove dead copper, pour order 42): 0,0 3000,0 3000,3000 0,3000
NetC6_2 on Top Layer "NETC6_2_L01_P033" (solid, remove dead copper, pour order 33): 1064.96,2085 1064.96,2060.63 1064.96,2035.04 1039.37,2035.04 1019.69,2035.04 1019.69,1910.31 1057.13,1872.87 1292.4,1872.87 1335,1830.28 1335,1590 1375,1550 1550,1550 1550,1995 1550,2085
NetC1_1 on Top Layer "NETC1_1_L01_P035" (solid, remove dead copper, pour order 35): 185,2035 295,2145 445,2145 475,2115 750,2115 804.37,2060.63 935.04,2060.63 935.04,2035 960.63,2035.04 985,2035.04 985,1910 390,1910 375,1925 295,1925
NetC6_2 on Top Layer "NETC6_2_L01_P036" (solid, remove dead copper, pour order 36): 1950,1350 1950,1800 2355,2205 2355,2600 2403.12,2648.12 2902.5,2648.12 2950,2600 2950,1502.5 2155,1502.5 2155,1420 2085,1350
NetC6_2 on Top Layer "NETC6_2_L01_P037" (solid, remove dead copper, pour order 37): 1064.96,885 1064.96,860.63 1064.96,835.04 1039.37,835.04 1019.69,835.04 1019.69,710.32 1055,675 1290,675 1510,675 1550,715 1550,1450 1370,1450 1335,1415 1335,905 1315,885
NetC13_1 on Top Layer "NETC13_1_L01_P038" (solid, remove dead copper, pour order 38): 935.05,865 935,840 935,835 980,835 985,830 985,710 590,710 500,710 390,710 390,820 355,855 295,855 185,965 295,1075 345,1075 535,1075 580,1030 710,1030 875,865
GND on Bottom Layer "Bottom Layer- GND" (solid, pour order 43): 0,0 3000,0 3000,3000 0,3000
GND on Signal Layer 1 "Signal Layer 1 - GND" (solid, pour order 44): 0,0 3000,0 3000,3000 0,3000
NetC6_2 on Signal Layer 2 "NETC6_2_L03_P041" (solid, remove dead copper, pour order 41): 1950,1350 1950,1800 2355,2205 2355,2600 2403.12,2648.12 2902.5,2648.12 2950,2600 2950,1530 2925,1505 2425,1505 2270,1350
NetC6_2 on Signal Layer 2 "NETC6_2_L03_P040" (solid, remove dead copper, pour order 40): 1064.96,2085 1064.96,2060.63 1064.96,2035.04 1019.69,1989.76 1019.69,1910.31 1057.13,1872.87 1292.4,1872.87 1345,1820.28 1345,1575 1370,1550 1550,1550 1550,2045 1510,2085
NetC6_2 on Signal Layer 2 "NETC6_2_L03_P039" (solid, remove dead copper, pour order 39): 1064.96,885 1064.96,860.63 1064.96,835.04 1039.37,835.04 1019.69,835.04 1019.69,710.32 1055,675 1290,675 1510,675 1550,715 1550,1450 1370,1450 1345,1425 1345,910 1320,885
GND on Signal Layer 2 "Signal Layer 2 - GND" (solid, pour order 46): 0,0 3000,0 3000,3000 0,3000

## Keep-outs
Keep-Out Layer:
  text ".Layer_Name" at -3541,-3279.49 h60

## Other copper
Top Layer:
  pour cut-out: 2153.5,1535 2930,1535 2962.5,1502.5 2962.5,1497.5 2930,1465 2153.5,1465
  pour cut-out: 47.5,2430 47.5,2395 252.5,2395 252.5,2430
  pour cut-out: 47.5,605 47.5,570 252.5,570 252.5,605
  pour cut-out: 950,2150 1050,2150 1050,2050 950,2050
  pour cut-out: 950,950 1050,950 1050,850 950,850
  text ".Layer_Name" at -3541,-3279.49 h60
Signal Layer 2:
  rectangle net NetC6_2: 1500,1350 1550,1450
Bottom Layer:
  text ".Layer_Name" at -3541,-3279.49 h60

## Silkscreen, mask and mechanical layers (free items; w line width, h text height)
Top Overlay:
  lines w10: 1570,1400.59 1640,1400.59 1657,1430.59 1691,1370.59 1725,1430.59 1759,1370.59 1793,1430.59 1827,1370.59 1844,1400.59 1914,1400.59 ; 1570,1600.59 1640,1600.59 1657,1630.59 1691,1570.59 1725,1630.59 1759,1570.59 1793,1630.59 1827,1570.59 1844,1600.59 1914,1600.59
  text "High Current Low Noise Parallel LDO Solution" at 1485,2735 h60
  text "Vout=" at 1135,1835 h40
  text "0.8V+" at 1350,1835 h40
  text "50mV" at 1350,1735 h40
  text "100mV" at 1350,1635 h40
  text "200mV" at 1350,1535 h40
  text "400mV" at 1350,1435 h40
  text "800mV" at 1350,1335 h40
  text "1.6V" at 1350,1235 h40
  text ".Layer_Name" at -3541,-3279.49 h60
Bottom Overlay:
  text ".Layer_Name" at -3541,-3279.49 h60
Top Paste:
  text ".Layer_Name" at -3541,-3279.49 h60
Bottom Paste:
  text ".Layer_Name" at -3541,-3279.49 h60
Top Solder:
  text ".Layer_Name" at -3541,-3279.49 h60
  text ".Layer_Name" at -3541,-3279.49 h60
Bottom Solder:
  text ".Layer_Name" at -3541,-3279.49 h60
Drill Guide:
  text ".Layer_Name" at -3541,-3279.49 h60
M1 Board Outline:
  lines w7: 0,0 0,3000 3000,3000 3000,1285 3000,0 1715,0 0,0
  text ".Layer_Name" at -3541,-3279.49 h60
M2 Board Dimensions:
  rectangle: -4118,-2696 -3993,-2571
  rectangle: -3993,-2821 -3618,-2696
  lines w7: -4118,-2696 -3118,-2696 ; -3993,-2821 -3993,-2571 ; -3868,-2821 -3868,-2571 ; -3618,-2821 -3618,-2571 ; -3368,-2821 -3368,-2571 ; -4118,-2821 -3118,-2821 -3118,-2571 -4118,-2571 -4118,-2821
  text ".Layer_Name" at -3541,-3279.49 h60
M3 3D STEP Top:
  text ".Layer_Name" at -3541,-3279.49 h60
M4 3D STEP Bottom:
  text ".Layer_Name" at -3541,-3279.49 h60
M5 Assembly Top:
  lines w10: -4410,-3351.17 2190,-3351.17 ; -4410,-3147.83 2192,-3147.83 ; -4410,-2944.5 -4410,-3554.5 -405,-3554.5 2192,-3554.5 2192,-2944.5 -4409.5,-2944.5 -4409.5,-3554.5 -2834,-3554.5 ; -1945,-3554.5 -1945,-2944.5 ; -678,-3147.83 -678,-2944.5 ; 162,-3147.83 162,-2944.5 ; 784,-3561 784,-3358.17
  text "COMPONENTS MARKED 'DNP' SHOULD NOT BE POPULATED." at -2964.5,-2739.5 h60
  text "ASSEMBLY VARIANT:" at -2965,-2855 h60
  text ".VariantName" at -1929,-2855 h60
  text "PCB VIEWED FROM TOP SIDE" at -4346.5,-3076.67 h60
  text "BOARD #:" at -1870,-3076.67 h60
  text ".PRJ_Number" at -1324.5,-3076.67 h60
  text "REV:" at -480,-3076.67 h60
  text ".PCB_Rev" at -188.5,-3076.67 h60
  text "SVN REV:" at 358,-3076.67 h60
  text ".VersionControl_RevNumber" at 864,-3076.67 h60
  text "TID #:" at -1870,-3280 h60
  text ".TID" at -1324.5,-3280 h60
  text "PLOT NAME =" at -4346.5,-3485.34 h60
  text ".plot_File_Name" at -3541,-3485.34 h60
  text "GENERATED    :" at -1868,-3485.34 h60
  text ".Print_Date" at -998.5,-3485.34 h60
  text ".Print_Time" at -269.5,-3485.34 h60
  text "TEXAS INSTRUMENTS" at 995,-3485.34 h60
M6 Assembly Bottom:
  lines w10: -4410.5,-3148.33 2191.5,-3148.33 ; -4408.5,-3351.67 2191.5,-3351.67 ; -3002.5,-3561.5 -3002.5,-3358.67 ; -2380.5,-3148.33 -2380.5,-2945 ; -1540.5,-3148.33 -1540.5,-2945 ; -273.5,-3555 -273.5,-2945 ; 615.5,-3555 2191,-3555 2191,-2945 -4410.5,-2945 -4410.5,-3555 -1813.5,-3555 2191.5,-3555 2191.5,-2945
  text "COMPONENTS MARKED 'DNP' SHOULD NOT BE POPULATED." at 1984,-2739 h60
  text ".VariantName" at 940,-2855 h60
  text "ASSEMBLY VARIANT:" at 1979,-2855 h60
  text ".VersionControl_RevNumber" at -3082.5,-3077.17 h60
  text "SVN REV:" at -2576.5,-3077.17 h60
  text ".PCB_Rev" at -2030,-3077.17 h60
  text "REV:" at -1738.5,-3077.17 h60
  text ".PRJ_Number" at -894,-3077.17 h60
  text "BOARD #:" at -348.5,-3077.17 h60
  text "PCB VIEWED FROM BOTTOM SIDE" at 2128,-3077.17 h60
  text ".TID" at -894,-3280.5 h60
  text "TID #:" at -348.5,-3280.5 h60
  text "TEXAS INSTRUMENTS" at -3213.5,-3485.84 h60
  text ".Print_Time" at -1949,-3485.84 h60
  text ".Print_Date" at -1220,-3485.84 h60
  text "GENERATED    :" at -350.5,-3485.84 h60
  text ".plot_File_Name" at 1322.5,-3485.84 h60
  text "PLOT NAME =" at 2128,-3485.84 h60
M9 Title Sheet:
  drawing of 57 lines, arcs and shapes, not listed
  text "1" at -3378.16,5615.5 h70
  text "2" at -882.5,5615.5 h70
  text "3" at 1606.84,5615.5 h70
  text "4" at 4113.51,5615.5 h70
  text "5" at 6612.5,5615.5 h70
  text "6" at 9117.5,5615.5 h70
  text "A" at -4534.5,4472.5 h70
  text "A" at 10265.5,4472.5 h70
  text "B" at -4534.5,2092.5 h70
  text "B" at 10265.5,2092.5 h70
  text "C" at -4534.5,-282.5 h70
  text "C" at 10265.5,-282.5 h70
  text "PROJECT TITLE:" at 7225.5,-2143.5 h45
  text "High Current Low Noise Parallel LDO Solution" at 7275.5,-2276.83 h70
  text "DESIGNED FOR:" at 7225.5,-2444.5 h45
  text "Public Release" at 7275.5,-2584.5 h70
  text "D" at -4534.5,-2652.5 h70
  text "D" at 10265.5,-2652.5 h70
  text "FILE NAME:" at 7225.5,-2744.5 h45
  text "TIDA-01232A.PcbDoc" at 7275.5,-2864.5 h70
  text "Texas Instruments (TI) and/or its licensors do not warrant the accuracy or completeness of this specification" at 2256,-3026.34 h45
  text "ENGINEER:" at 7225.5,-3034.5 h45
  text "LAYOUT BY:" at 8730.5,-3034.5 h45
  text "or any information contained therein. TI and/or its licensors do not warrant that this design will meet" at 2211.01,-3139 h45
  text "Nicolas Roman" at 7275.5,-3189.49 h70
  text "Nicolas Roman" at 8781,-3189.49 h70
  text "the specifications, will be suitable for your application or fit for any particular purpose, or will operate in" at 2211.01,-3251.67 h45
  text ".Layer_Name" at -3541,-3279.49 h60
  text "ALTIUM DESIGNER VERSION:" at 8730.5,-3344.5 h45
  text "an implementation. TI and/or its licensors do not warrant that the design is production worthy. You should" at 2211.01,-3364.33 h45
  text "completely validate and test your design implementation to confirm the system functionality for your application." at 2256,-3477 h45
  text ".print_Scale" at 7275.5,-3477.83 h70
  text ".Application_BuildNumber" at 8781,-3477.83 h70
  text "1" at -3378.16,-3684.5 h70
  text "2" at -882.5,-3684.5 h70
  text "3" at 1606.84,-3684.5 h70
  text "4" at 4113.51,-3684.5 h70
  text "5" at 6612.5,-3684.5 h70
  text "6" at 9117.5,-3684.5 h70
M10 Fab Notes:
  drawing of 185 lines, arcs and shapes, not listed
  text "DESIGN INFORMATION" at 8263.02,3489 h60
  text "MIN. TRACK WIDTH:" at 7618.46,3309 h60
  text "8" at 8714.7,3309 h60
  text "MIL" at 8869.46,3309 h60
  text "MIN. CLEARANCE:" at 7618.46,3177 h60
  text "0.2" at 8654.7,3177 h60
  text "mm" at 8869.46,3177 h60
  text "MIN. VIA PAD SIZE:" at 7618.46,3045 h60
  text "24" at 8684.71,3045 h60
  text "MIL" at 8869.46,3045 h60
  text "0.05mm (2MIL)" at 8313.46,2903.29 h60
  text "MINIMUM ANNULAR RING" at 7289.23,2899 h60
  text "EXTERNAL" at 9021.46,2899 h60
  text "PER" at 7489.23,2781 h60
  text "IPC-D-275 CLASS 2 LEVEL C" at 7709.23,2781 h60
  text "MIL, HOLES" at 9197.46,2668.71 h60
  text "+/-" at 8805,2668 h60
  text "+/-" at 9659,2668 h60
  text "REGISTRATION TOLERANCES:" at 7289.23,2663 h60
  text "METAL" at 8489,2663 h60
  text "5" at 9065.2,2663 h60
  text "3" at 9898.2,2663 h60
  text "MIL" at 10014.46,2663 h60
  text "MATERIAL:" at 7214.46,2453.54 h60
  text "FR-4 High Tg" at 8200.9,2313.21 h60
  text "FR-408" at 7635.46,2304.64 h60
  text "X" at 8047.46,2304.64 h60
  text "OTHER" at 9123.46,2304.64 h60
  text "62 MIL (1.6mm) +/-10%" at 7955.56,2141.92 h60
  text "THICKNESS:" at 7289.23,2137.64 h60
  text "X" at 7827.4,2137.64 h60
  text "OTHER" at 9240.46,2137.64 h60
  text "TOLERANCE:" at 7289.23,1979.64 h60
  text "X" at 8128.53,1979.64 h60
  text "ANSI IPC-6012 TYPE 3 CLASS 2" at 8315.48,1979.64 h60
  text "OTHER +/-" at 8315.46,1823.64 h60
  text "BOW & TWIST:" at 7289.23,1666.64 h60
  text "X" at 8128.53,1666.64 h60
  text "ANSI IPC-6012 TYPE 3 CLASS 2" at 8315.48,1666.64 h60
  text "OTHER +/-" at 8315.46,1508.13 h60
  text "DRILLING:" at 7214.46,1369.64 h60
  text "REFERENCE:" at 7289.23,1252.64 h60
  text "X" at 7937.46,1252.64 h60
  text "AS SHOWN" at 8124.46,1252.64 h60
  text "X" at 8838.46,1252.64 h60
  text "NC_DRILL FILES" at 8975.46,1252.64 h60
  text "PTH MIN COPPER THICKNESS:" at 7289.23,1094.64 h60
  text "X" at 8639.46,1094.64 h60
  text "1MIL" at 8776.46,1094.64 h60
  text "OTHER" at 9273.46,1094.64 h60
  text "BOARD FINISH:" at 7214.46,935.64 h60
  text "SILKSCREEN:" at 7369.68,817.64 h60
  text "X" at 8318.46,817.64 h60
  text "TOP" at 8444.46,817.64 h60
  text "BOTTOM" at 8955.46,817.64 h60
  text "SILKSCREEN COLOR:" at 7369.68,650.64 h60
  text "X" at 8317.42,650.64 h60
  text "WHITE" at 8444.46,650.64 h60
  text "OTHER" at 8955.46,650.64 h60
  text "SOLDER RESIST COLOR:" at 7369.68,480.64 h60
  text "GREEN" at 8064.46,321.44 h60
  text "BLUE" at 8655.46,321.44 h60
  text "OTHER" at 9193.46,321.44 h60
  text "X" at 7940,320 h60
  text "IMMERSION GOLD (ENIG)" at 8275.46,132.92 h60
  text "ENEPIG" at 9613,129.64 h60
  text "SURFACE FINISH:" at 7214.46,128.64 h60
  text "X" at 8088.51,128.64 h60
  text "IMM. TIN/SILVER OR EQUIV" at 7544,-28.36 h60
  text "OTHER" at 8975.46,-28.36 h60
  text "ARRAY/PANEL:" at 7214.46,-207.36 h60
  text "CUT AND TRIM PER MECH LAYER 1" at 8275.46,-211.65 h60
  text "N.C. ROUTE" at 8275.46,-363.36 h60
  text "X" at 8954.46,-363.36 h60
  text "V. SCORE" at 9141.46,-363.36 h60
  text "CERTIFICATION:" at 7214.46,-500.36 h60
  text "MATERIALS AND WORKMANSHIP FOR ALL PCBS" at 7939.46,-500.36 h60
  text "TO MEET OR EXCEED THE REQUIREMENTS OF:" at 7939.46,-598.36 h60
  text "X" at 7565.96,-734.87 h60
  text "ANSI IPC-A-600F CLASS ->" at 7704.96,-734.87 h60
  text "X" at 9344.02,-734.87 h60
  text "2" at 9462.96,-734.86 h60
  text "1" at 9147.96,-736.36 h60
  text "3" at 9816.96,-736.36 h60
  text "X" at 7568.02,-894.36 h60
  text "UL 94V-0" at 7704.96,-894.36 h60
  text "X" at 8380.02,-894.36 h60
  text "RoHS" at 8516.96,-894.36 h60
  text "OTHER" at 9161.36,-894.36 h60
  text "PER ORDER" at 9558.42,-894.36 h60
  text "ADDITIONAL REQUIREMENTS:" at 7214.46,-1035.36 h60
  text "MICROSECTION:" at 7289.23,-1150.36 h60
  text "YES" at 8194.96,-1150.36 h60
  text "REQUIRED" at 9056.46,-1306.51 h60
  text "BARE BOARD ELEC. TEST:" at 7289.23,-1309.36 h60
  text "NONE" at 8594.96,-1309.36 h60
  text "X" at 8929.46,-1309.36 h60
  text "PER ORDER" at 9648.46,-1309.36 h60
  text "MANUFACTURER'S UL:" at 7289.23,-1466.36 h60
  text "RAIL" at 8454.96,-1470.65 h60
  text "METAL" at 8946.77,-1470.65 h60
  text "X" at 9322,-1471 h60
  text "SILK" at 9458.46,-1470.65 h60
  text ".Layer_Name" at -3541,-3279.49 h60
M11 Gerber Information:
  lines w10: -4410,-3351.17 2190,-3351.17 ; -4410,-3147.83 2192,-3147.83 ; -4410,-2944.5 -4410,-3554.5 -405,-3554.5 2192,-3554.5 2192,-2944.5 -4409.5,-2944.5 -4409.5,-3554.5 -2834,-3554.5 ; -1945,-3554.5 -1945,-2944.5 ; -678,-3147.83 -678,-2944.5 ; 162,-3147.83 162,-2944.5 ; 784,-3561 784,-3358.17
  text "ALL ARTWORK VIEWED FROM TOP SIDE" at -4346.5,-3076.67 h60
  text "BOARD #:" at -1870,-3076.67 h60
  text ".PRJ_Number" at -1324.5,-3076.67 h60
  text "REV:" at -480,-3076.67 h60
  text ".PCB_Rev" at -188.5,-3076.67 h60
  text "SVN REV:" at 358,-3076.67 h60
  text ".VersionControl_RevNumber" at 864,-3076.67 h60
  text "LAYER NAME =" at -4346.5,-3279.49 h60
  text "TID #:" at -1870,-3280 h60
  text ".TID" at -1324.5,-3280 h60
  text "PLOT NAME =" at -4346.5,-3485.34 h60
  text ".plot_File_Name" at -3541,-3485.34 h60
  text "GENERATED    :" at -1868,-3485.34 h60
  text ".Print_Date" at -998.5,-3485.34 h60
  text ".Print_Time" at -269.5,-3485.34 h60
  text "TEXAS INSTRUMENTS" at 995,-3485.34 h60
M12 Stackup:
  drawing of 269 lines, arcs and shapes, not listed
  text "Layer" at 5575.08,5101.5 h60
  text "Name" at 5984.99,5101.5 h60
  text "Material" at 6924.73,5101.5 h60
  text "Thickness" at 7784.5,5101.5 h60
  text "Constant" at 8434.34,5101.5 h60
  text "Board Layer Stack" at 9004.2,5101.5 h60
  text "1" at 5575.08,4981.5 h60
  text "Top Overlay" at 5984.99,4981.5 h60
  text "2" at 5575.08,4861.5 h60
  text "Top Solder" at 5984.99,4861.5 h60
  text "Solder Resist" at 6924.73,4861.5 h60
  text "0.40mil" at 7784.5,4861.5 h60
  text "3.5" at 8434.34,4861.5 h60
  text "3" at 5575.08,4741.5 h60
  text "Top Layer" at 5984.99,4741.5 h60
  text "Copper" at 6924.73,4741.5 h60
  text "2.80mil" at 7784.5,4741.5 h60
  text "4" at 5575.08,4621.5 h60
  text "Dielectric 1" at 5984.99,4621.5 h60
  text "8.00mil" at 7784.5,4621.5 h60
  text "4.2" at 8434.34,4621.5 h60
  text "5" at 5575.08,4501.5 h60
  text "Signal Layer 1" at 5984.99,4501.5 h60
  text "Copper" at 6924.73,4501.5 h60
  text "1.40mil" at 7784.5,4501.5 h60
  text "6" at 5575.08,4381.5 h60
  text "Dielectric 2" at 5984.99,4381.5 h60
  text "FR-4" at 6924.73,4381.5 h60
  text "40.00mil" at 7784.5,4381.5 h60
  text "4.2" at 8434.34,4381.5 h60
  text "7" at 5575.08,4261.5 h60
  text "Signal Layer 2" at 5984.99,4261.5 h60
  text "Copper" at 6924.73,4261.5 h60
  text "1.40mil" at 7784.5,4261.5 h60
  text "8" at 5575.08,4141.5 h60
  text "Dielectric 3" at 5984.99,4141.5 h60
  text "8.00mil" at 7784.5,4141.5 h60
  text "4.2" at 8434.34,4141.5 h60
  text "9" at 5575.08,4021.5 h60
  text "Bottom Layer" at 5984.99,4021.5 h60
  text "Copper" at 6924.73,4021.5 h60
  text "2.80mil" at 7784.5,4021.5 h60
  text "10" at 5575.08,3901.5 h60
  text "Bottom Solder" at 5984.99,3901.5 h60
  text "Solder Resist" at 6924.73,3901.5 h60
  text "1.40mil" at 7784.5,3901.5 h60
  text "3.5" at 8434.34,3901.5 h60
  text ".Layer_Name" at -3541,-3279.49 h60
M13 Component Bodies Top:
  text ".Layer_Name" at -3541,-3279.49 h60
M14 Component Bodies Bottom:
  text ".Layer_Name" at -3541,-3279.49 h60
M15 Courtyards Top:
  text ".Layer_Name" at -3541,-3279.49 h60
M16 Courtyards Bottom:
  text ".Layer_Name" at -3541,-3279.49 h60
Drill Drawing:
  lines w10: 4056.09,2540.02 4111.34,2540.02 4111.34,2595.27 4056.09,2595.27 4056.09,2540.02 ; 4056.09,2664.34 4083.72,2678.15 4111.34,2664.34 4097.53,2691.96 4111.34,2719.59 4083.72,2705.78 4056.09,2719.59 4069.9,2691.96 4056.09,2664.34 ; 4056.09,2816.28 4083.72,2788.66 4111.34,2816.28 4083.72,2843.91 4056.09,2816.28
  lines w12: 4006,2502.72 5984.02,2502.72 ; 4006,2875.68 5984.02,2875.68 ; 4343.86,2378.4 4343.86,3000 ; 4675.86,2378.4 4675.86,3000 ; 5312.43,2378.4 5312.43,3000 ; 5571.57,2378.4 5571.57,3000 ; 4006,2378.4 5984.02,2378.4 5984.02,3000 4006,3000 4006,2378.4
  text "Symbol" at 4080.59,2912.98 h72
  text "Quantity" at 4381.16,2912.98 h72
  text "Finished Hole Size" at 4713.16,2912.98 h72
  text "Plated" at 5349.72,2912.98 h72
  text "Hole Type" at 5608.86,2912.98 h72
  text "127" at 4381.16,2788.66 h60
  text "10.00mil (0.254mm)" at 4713.16,2788.66 h60
  text "PTH" at 5349.72,2788.66 h60
  text "Round" at 5608.86,2788.66 h60
  text "8" at 4381.16,2664.34 h60
  text "27.56mil (0.700mm)" at 4713.16,2664.34 h60
  text "PTH" at 5349.72,2664.34 h60
  text "Round" at 5608.86,2664.34 h60
  text "34" at 4381.16,2540.02 h60
  text "40.16mil (1.020mm)" at 4713.16,2540.02 h60
  text "PTH" at 5349.72,2540.02 h60
  text "Round" at 5608.86,2540.02 h60
  text "169 Total" at 4381.16,2415.7 h60
  text ".Layer_Name" at -3541,-3279.49 h60

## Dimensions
0,0 to 0,3000 on M2 Board Dimensions
0,0 to 3000,0 on M2 Board Dimensions
-4118,-2821 to -3118,-2821 on M2 Board Dimensions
